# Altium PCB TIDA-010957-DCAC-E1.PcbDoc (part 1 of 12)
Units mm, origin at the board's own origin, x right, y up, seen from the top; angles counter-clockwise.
Board outline 300 x 300 mm, 4 copper layers (Top Layer, Layer 1, Layer 2, Bottom Layer), stack 1.787 mm thick; 1159 components, 619 nets, 3431 pads, 2942 vias.
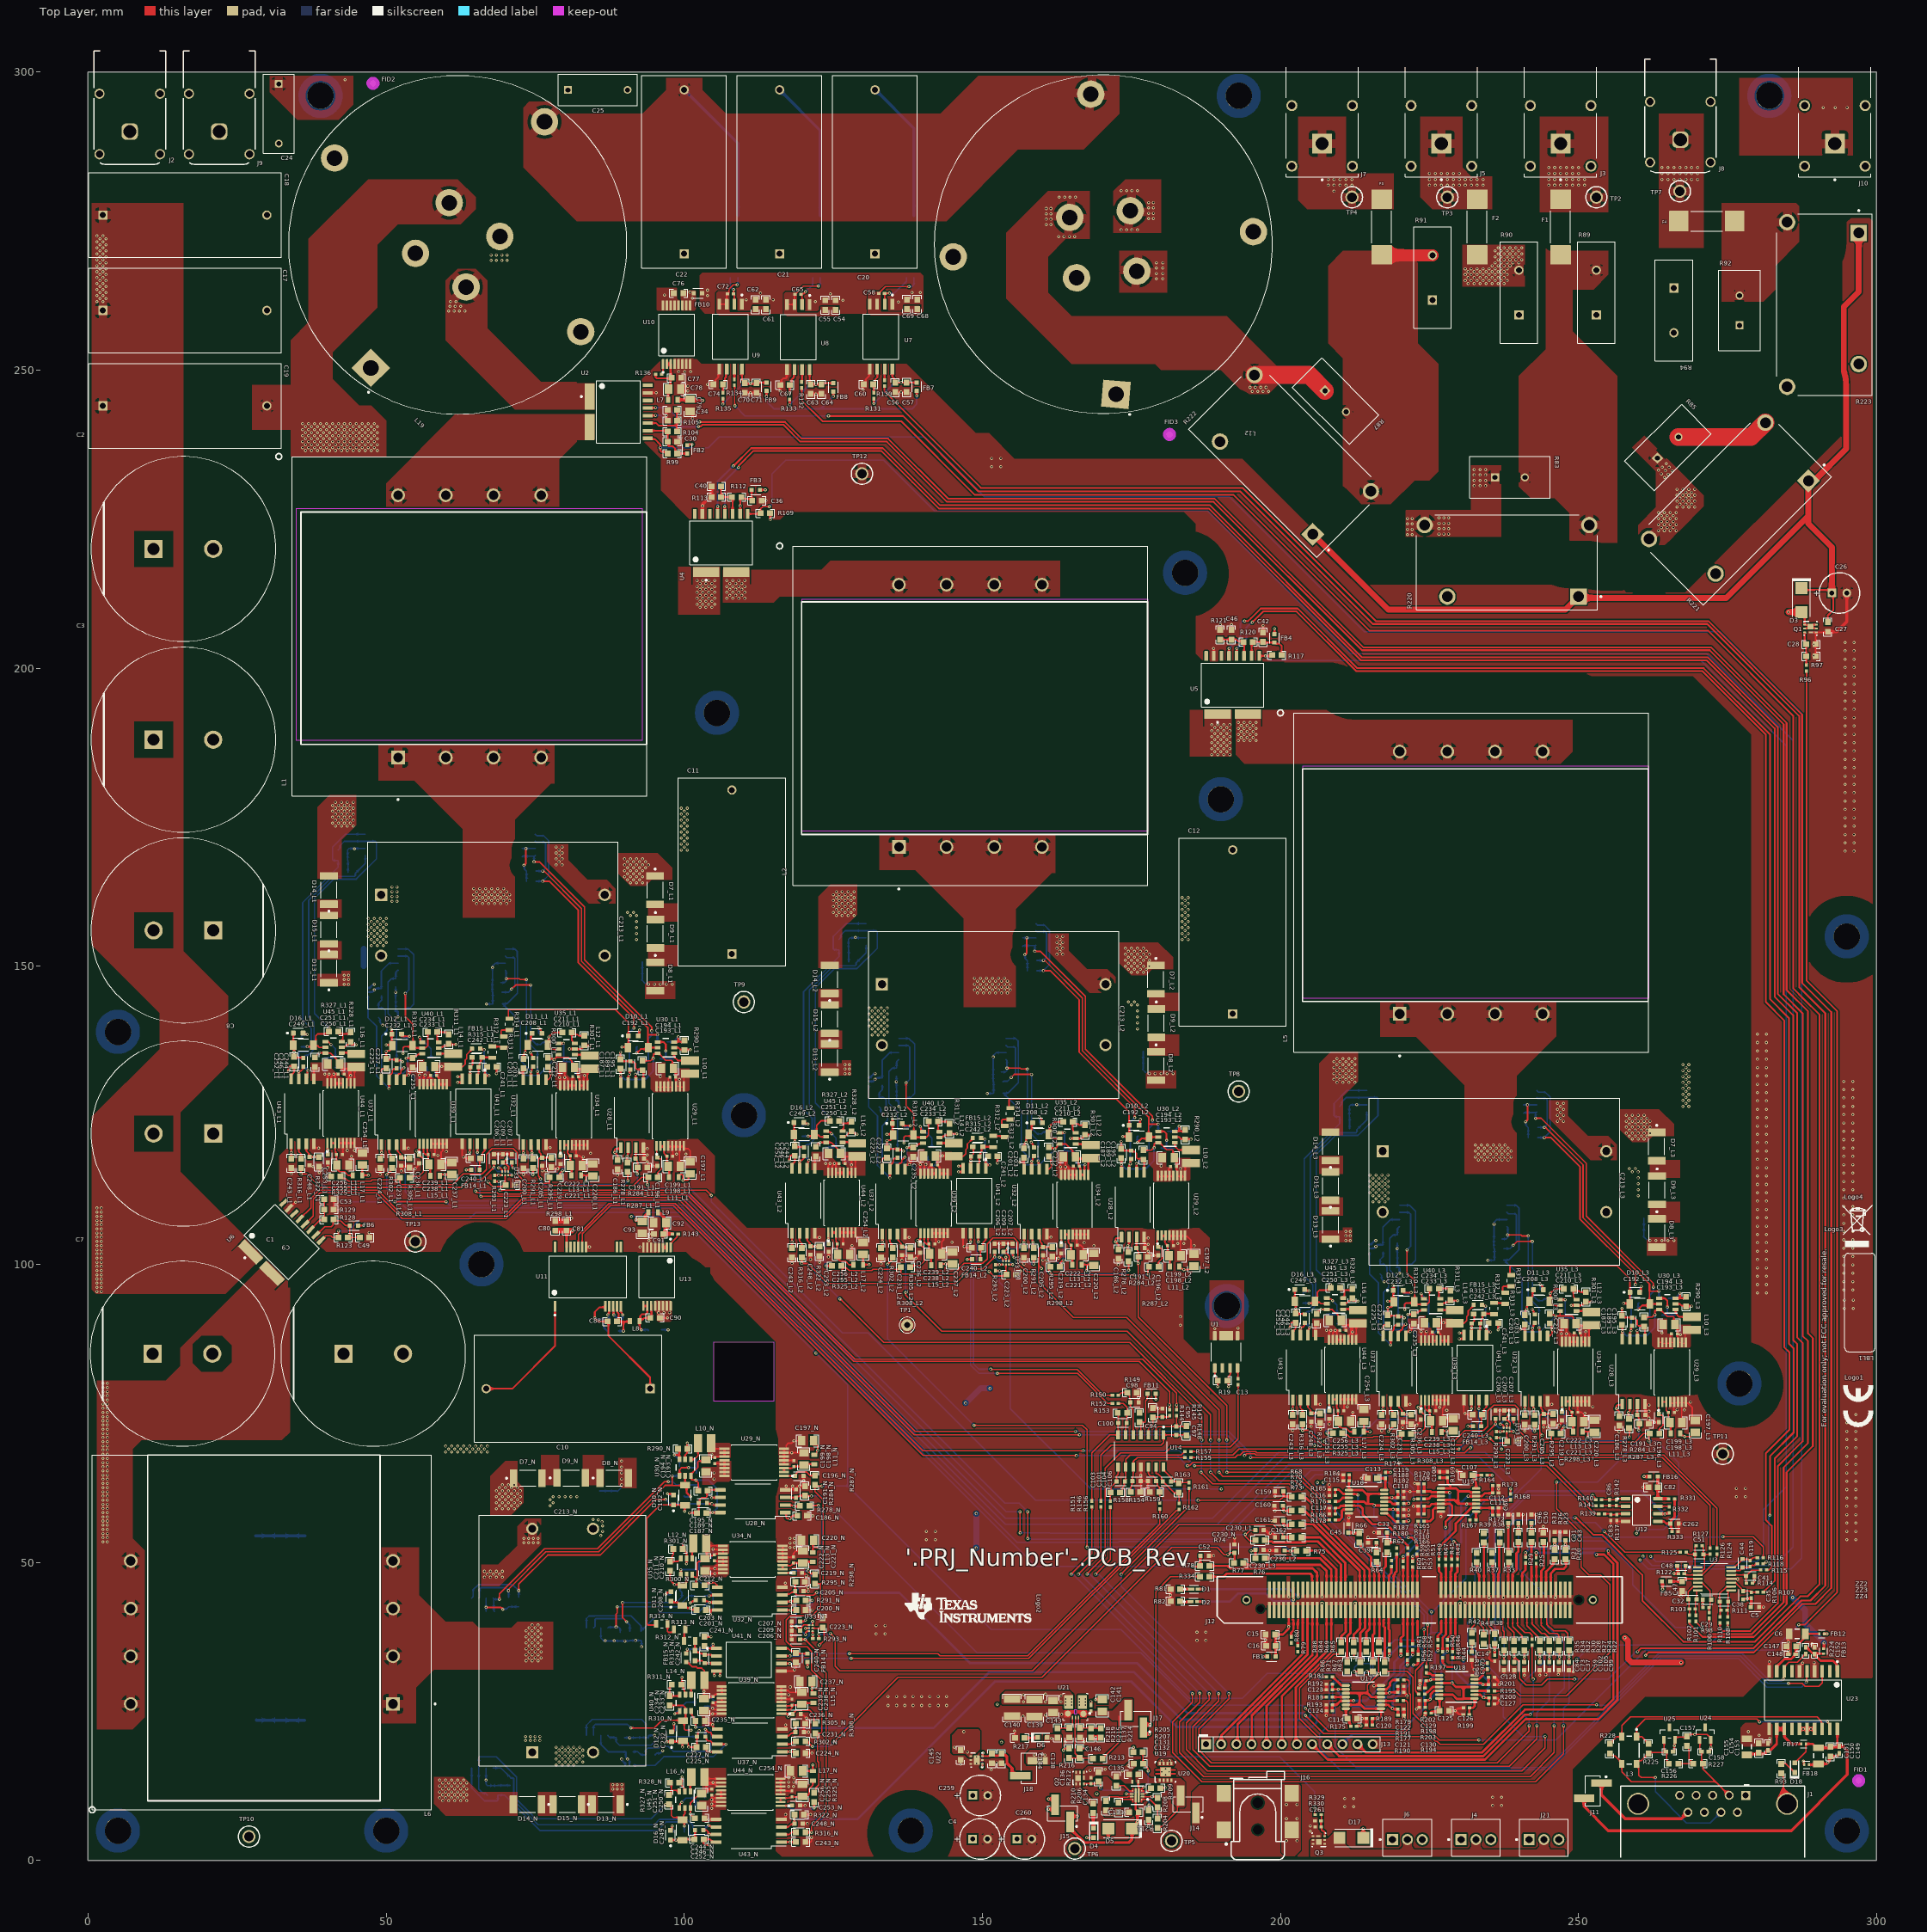
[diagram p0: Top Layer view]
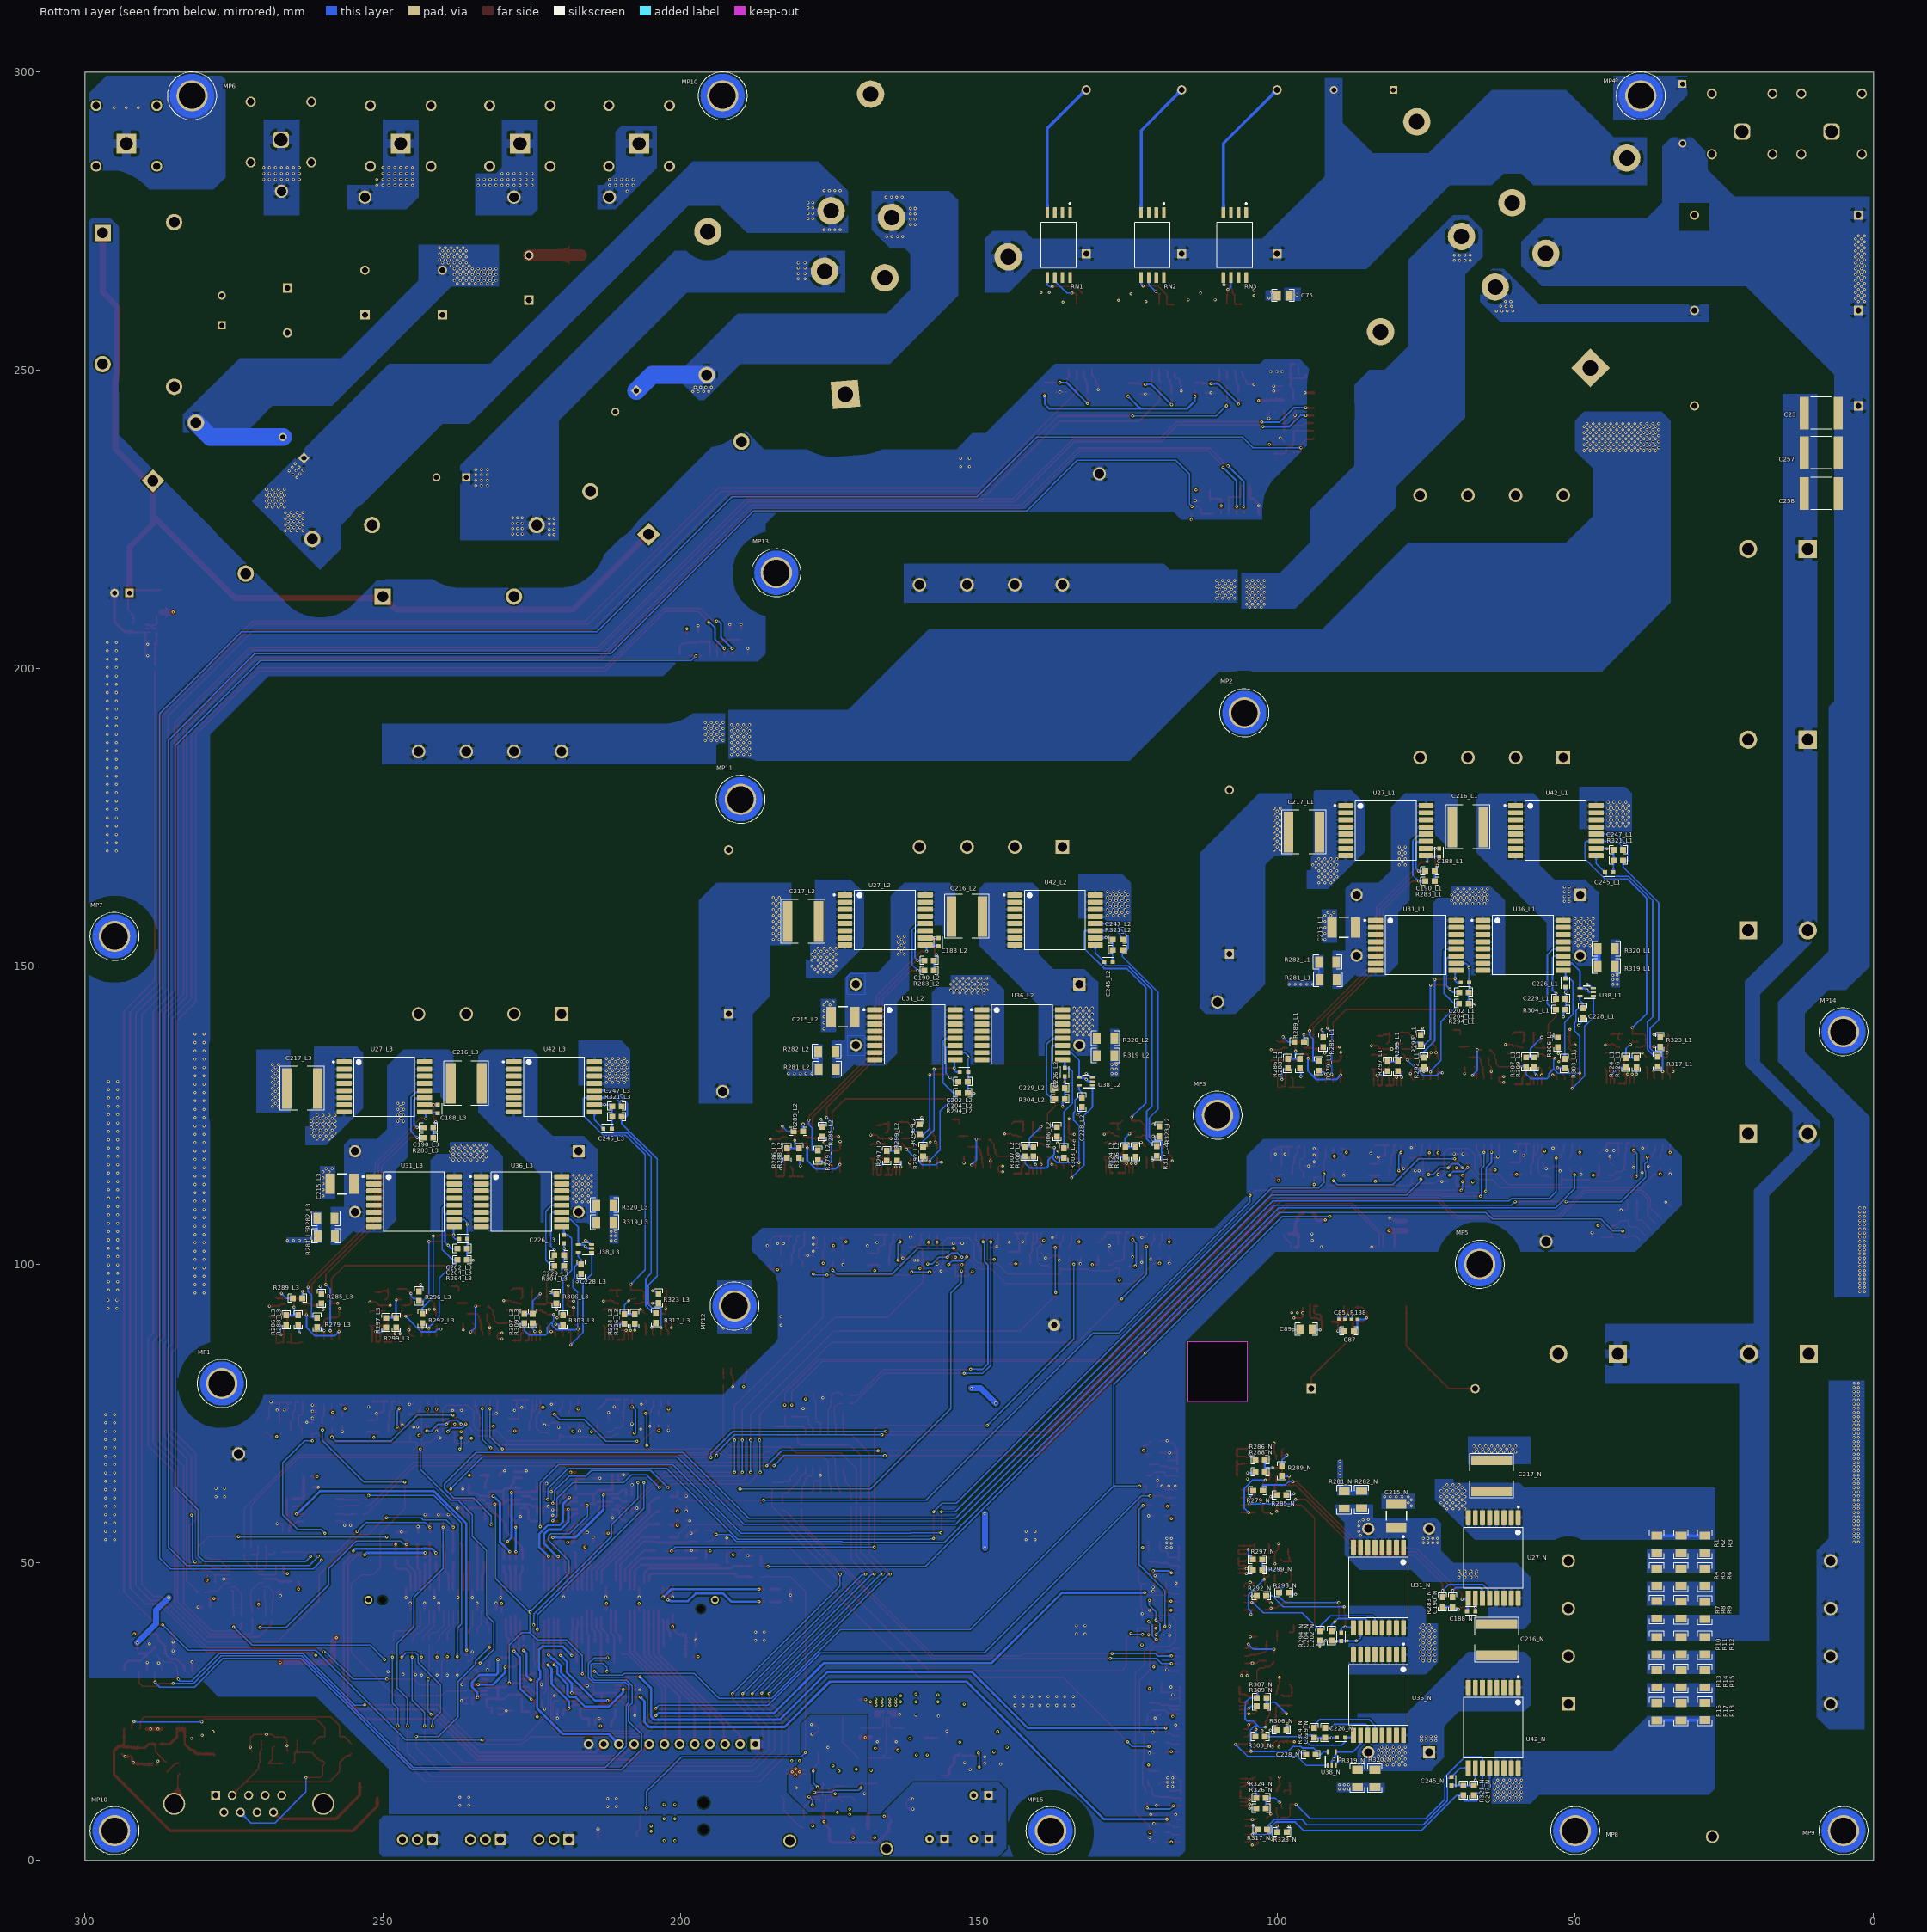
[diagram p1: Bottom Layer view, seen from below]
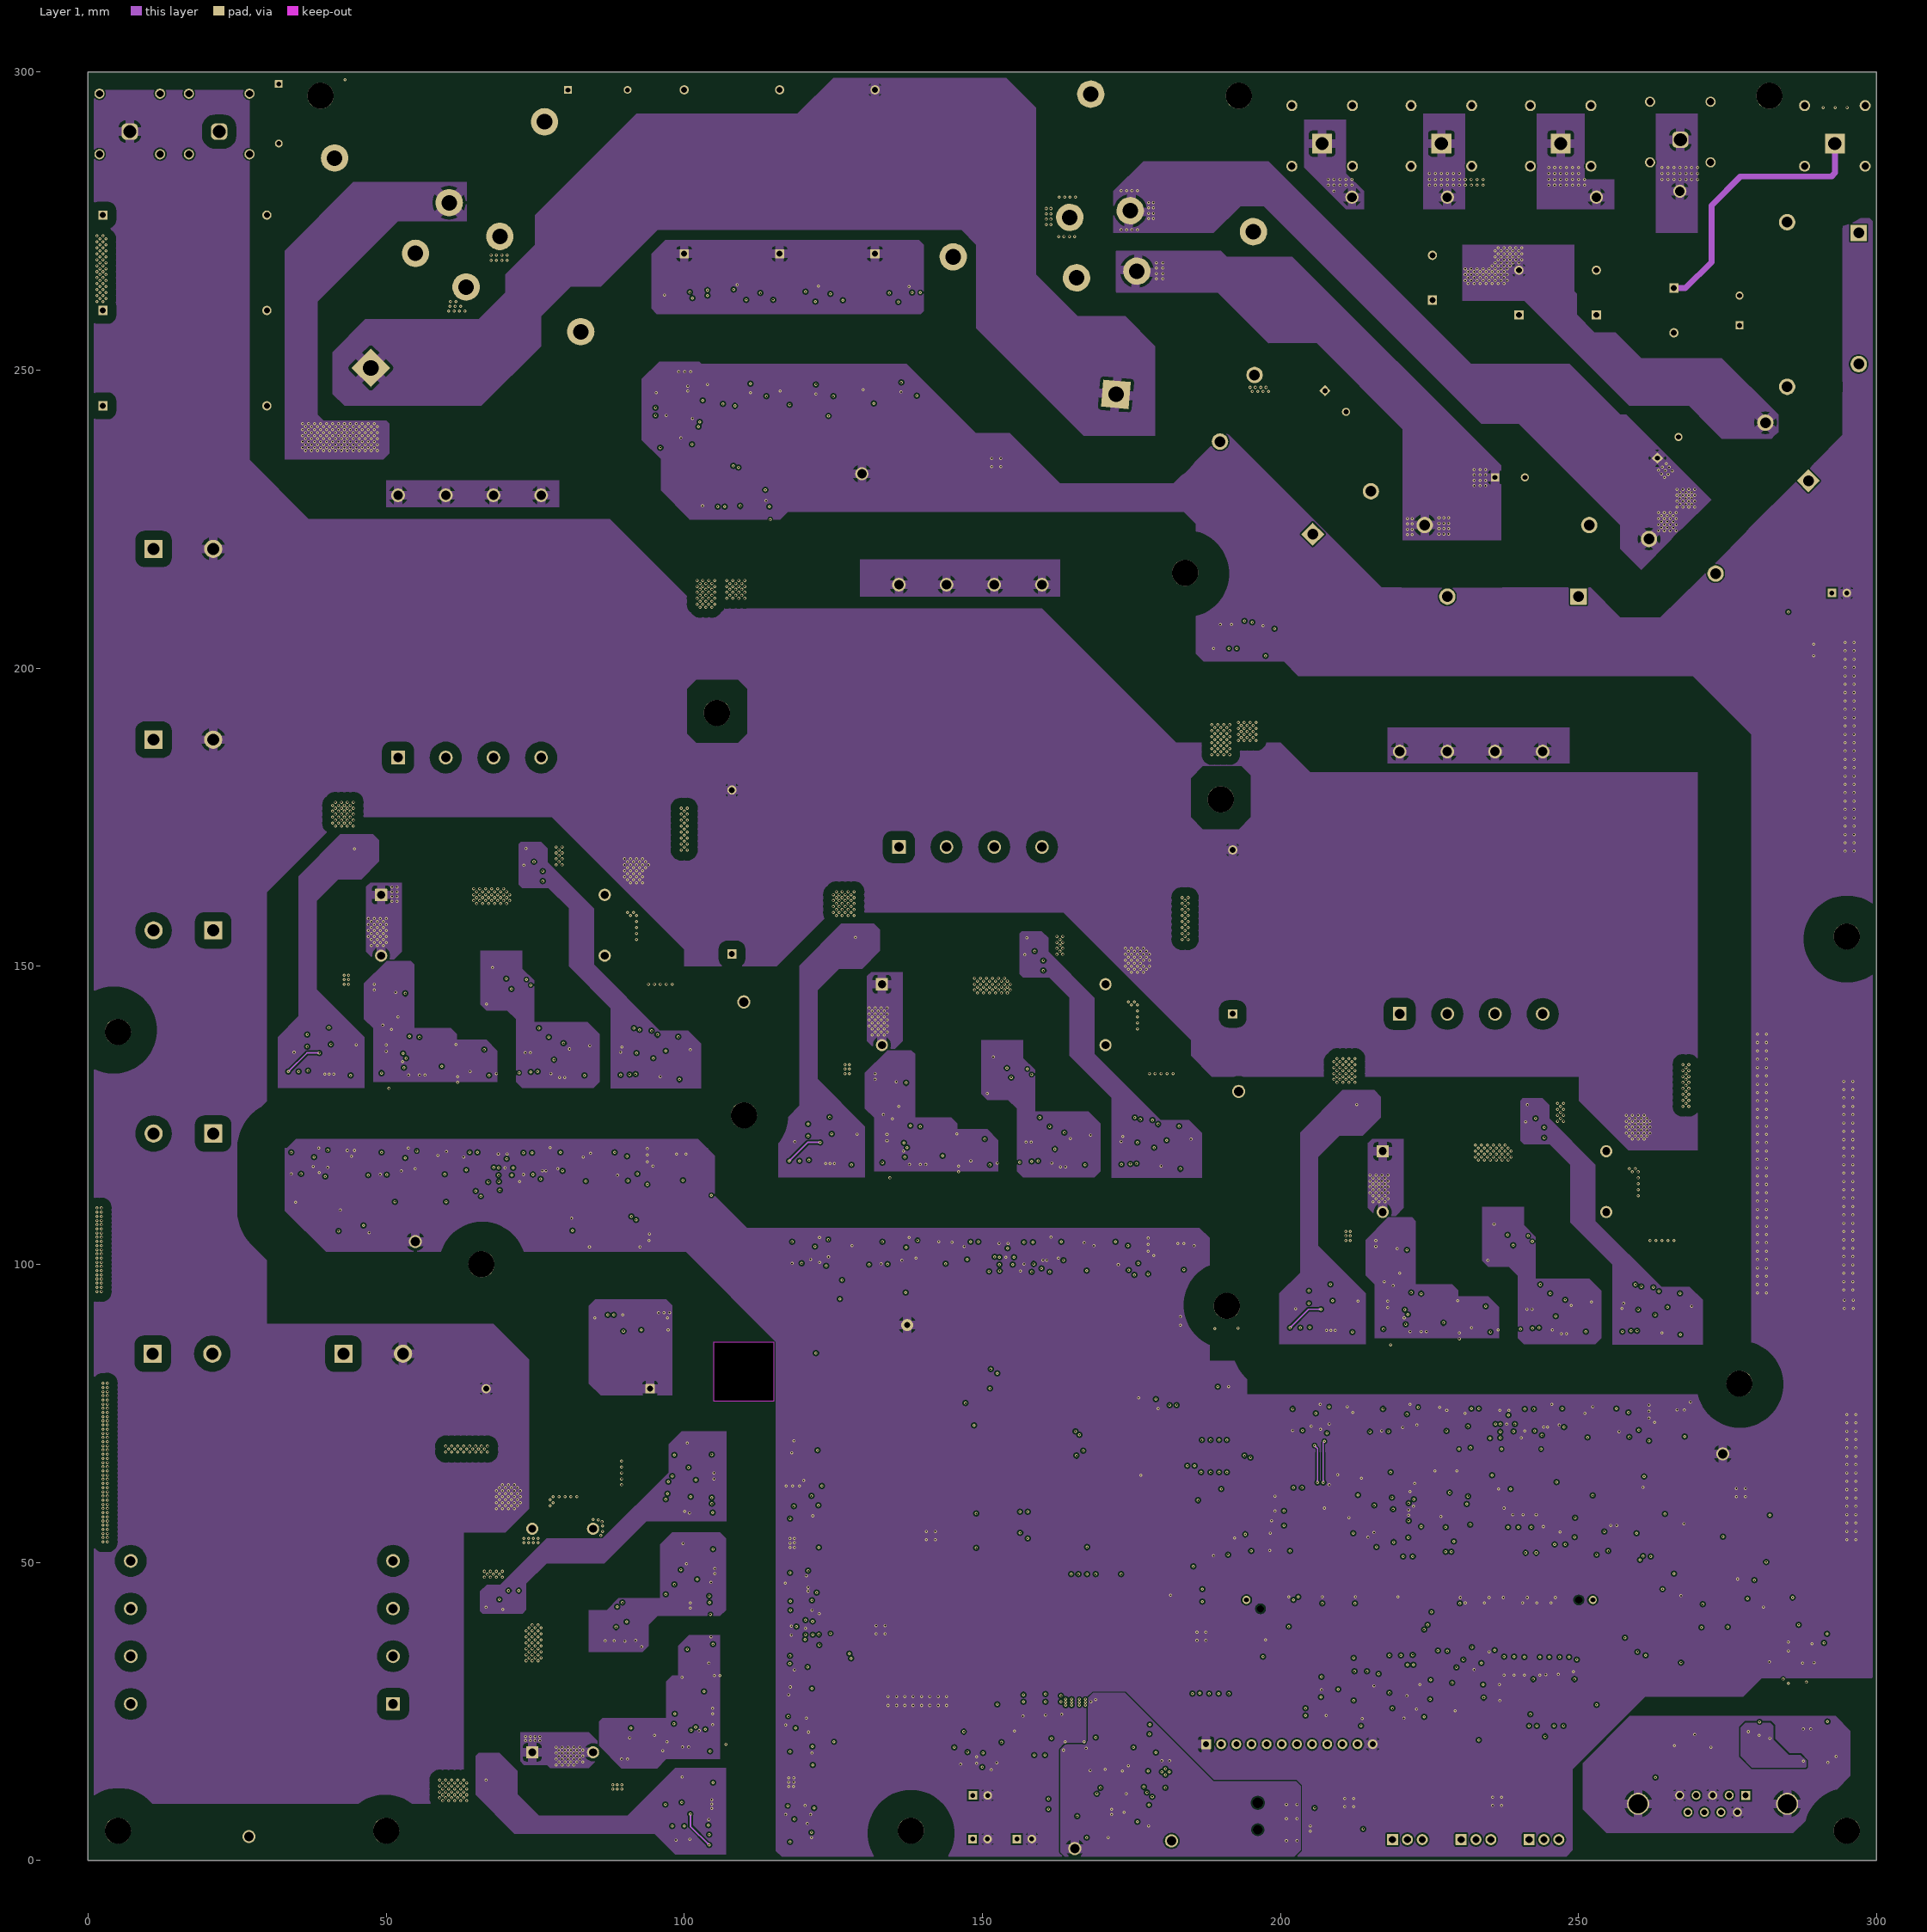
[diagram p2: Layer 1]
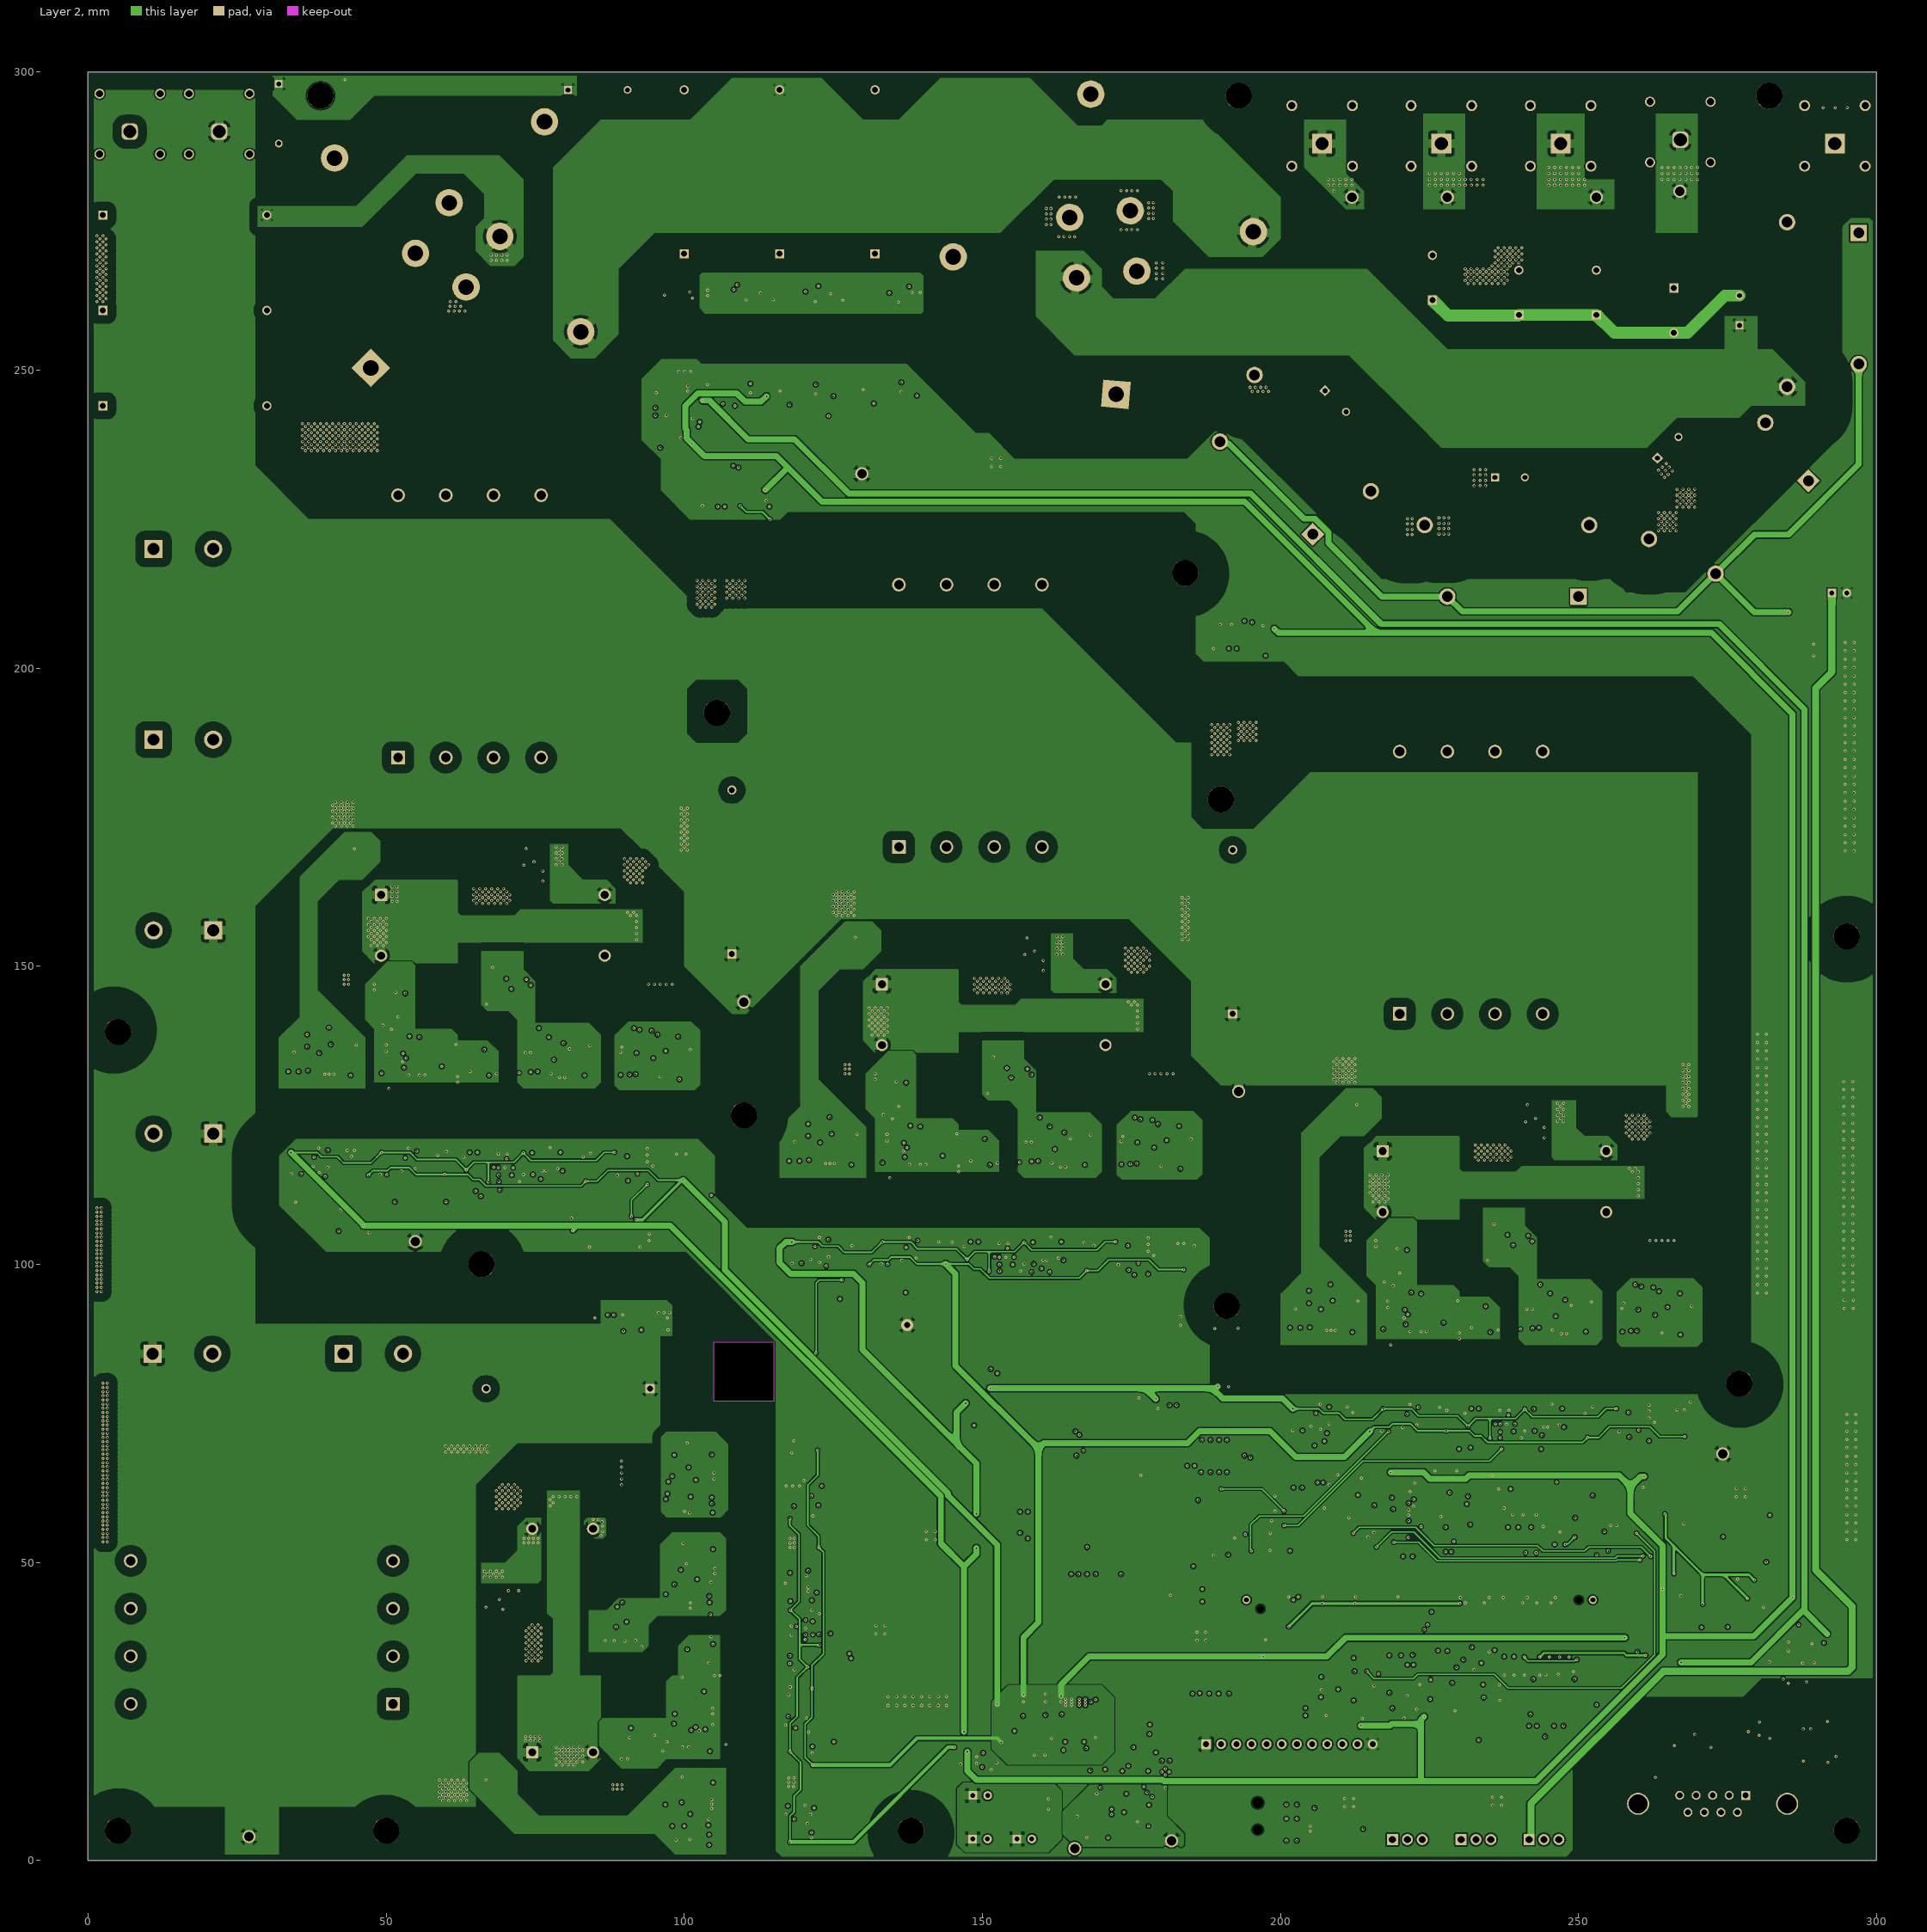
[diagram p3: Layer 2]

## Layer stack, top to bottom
Top Solder: solder mask 0.0102, Solder Resist, Dk 3.5
Top Layer: signal copper 0.0356
Dielectric 1: prepreg 0.0711, PP-006, Dk 4.1
Layer 1: signal copper 0.035
Dielectric1: core 1.5037, FR-4 High Tg, Dk 4.8
Layer 2: signal copper 0.035
Dielectric 2: prepreg 0.0711, PP-006, Dk 4.1
Bottom Layer: signal copper 0.0356
Bottom Solder: solder mask 0.0102, Solder Resist, Dk 3.5

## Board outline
0,0 300,0 300,300 0,300
cut-out: 105,77 105,87 115,87 115,77

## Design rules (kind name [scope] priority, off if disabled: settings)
AcuteAngle [All] p1: minimum=4.50000000000000E+0001 checktracksonly=FALSE
AssemblyTestPointUsage [All] p1: valid=2
BoardOutlineClearance BoardOutlineClearance_MountingHoles [OnCopper and InComponentClass('Mounting Holes')] p1: gap=1 ignorepadtopadclearanceinfootprint=FALSE
BoardOutlineClearance BoardOutlineClearance_Poly [OnCopper and IsPoly] p2: gap=0.635 ignorepadtopadclearanceinfootprint=FALSE
BoardOutlineClearance [OnCopper and Not InComponentClass('Logo') and not InComponentClass('FiducialMark') and not InRegion(1000,500,4000,800) and not InPoly] p3: gap=1.016 ignorepadtopadclearanceinfootprint=FALSE
Clearance "POS NEG DC Middle TOP" [(InNetClass('DC PLUS') or InNetClass('DC MINUS')) vs ((InNetClass('DC MIDDLE'))) And( OnLayer('Top Layer') Or OnLayer('Bottom Layer') )] p1: gap=3 ignorepadtopadclearanceinfootprint=TRUE
Clearance "Line to Line Top Bottom L1 to L2 L3" [(InNetClass('L1_HV')) And( OnLayer('Top Layer') Or OnLayer('Bottom Layer') ) vs ( InNetClass('L2_HV') Or InNetClass('L3_HV')) And( OnLayer('Top Layer') Or OnLayer('Bottom Layer') )] p2: gap=2.5 ignorepadtopadclearanceinfootprint=TRUE
Clearance "Line to Line inner L1 to L2 L3_1" [(InNetClass('L1_HV')) And( OnLayer('Top Layer') Or OnLayer('Bottom Layer') ) vs ( InNetClass('L2_HV') Or InNetClass('L3_HV')) And( not( OnLayer('Top Layer') Or OnLayer('Bottom Layer')) )] p3: gap=2.5 ignorepadtopadclearanceinfootprint=TRUE
Clearance "Line to Line Top Bottom L2 to L1 L3" [( InNetClass('L2_HV') ) And( OnLayer('Top Layer') Or OnLayer('Bottom Layer') ) vs (InNetClass('L1_HV')  Or InNetClass('L3_HV')) And( OnLayer('Top Layer') Or OnLayer('Bottom Layer') )] p4: gap=2.5 ignorepadtopadclearanceinfootprint=TRUE
Clearance "Line to Line Inner L2 to L1 L3_1" [( InNetClass('L2_HV') ) And( OnLayer('Top Layer') Or OnLayer('Bottom Layer') ) vs (InNetClass('L1_HV')  Or InNetClass('L3_HV')) And( not( OnLayer('Top Layer') Or OnLayer('Bottom Layer')) )] p5: gap=2.5 ignorepadtopadclearanceinfootprint=TRUE
Clearance "Line to Line Top Bottom L3 to L2 L1" [( InNetClass('L3_HV')) And( OnLayer('Top Layer') Or OnLayer('Bottom Layer') ) vs (InNetClass('L1_HV') Or InNetClass('L2_HV') ) And( OnLayer('Top Layer') Or OnLayer('Bottom Layer') )] p6: gap=2.5 ignorepadtopadclearanceinfootprint=TRUE
Clearance "Line to Line inner L3 to L2 L1_1" [( InNetClass('L3_HV')) And( OnLayer('Top Layer') Or OnLayer('Bottom Layer') ) vs (InNetClass('L1_HV') Or InNetClass('L2_HV') ) And(  not( OnLayer('Top Layer') Or OnLayer('Bottom Layer')) )] p7: gap=2.5 ignorepadtopadclearanceinfootprint=TRUE
Clearance "POS NEG TOP" [(InNetClass('DC PLUS')) vs ((InNetClass('DC MINUS'))) And( OnLayer('Top Layer') Or OnLayer('Bottom Layer') )] p8: gap=3 ignorepadtopadclearanceinfootprint=TRUE
Clearance "POS NEG Inner" [(InNetClass('DC PLUS')) vs ((InNetClass('DC MINUS'))) And( NOT ( OnLayer('Top Layer') Or OnLayer('Bottom Layer')))] p9: gap=1.5 ignorepadtopadclearanceinfootprint=TRUE
Clearance "POS NEG DC Middle Inner" [(InNetClass('DC PLUS') or InNetClass('DC MINUS')) vs ((InNetClass('DC MIDDLE'))) And( NOT ( OnLayer('Top Layer') Or OnLayer('Bottom Layer')))] p10: gap=1.5 ignorepadtopadclearanceinfootprint=TRUE
Clearance "Line and DC Rails EXT" [(InNetClass('L1_HV') Or InNetClass('L2_HV') Or InNetClass('L3_HV') Or InNetClass('LN_HV')) vs (InNetClass('DC PLUS') or InNetClass('DC MINUS')) And( ( OnLayer('Top Layer') Or OnLayer('Bottom Layer')) )] p11: gap=3 ignorepadtopadclearanceinfootprint=TRUE
Clearance "Line and DC Rails INT" [(InNetClass('L1_HV') Or InNetClass('L2_HV') Or InNetClass('L3_HV')Or InNetClass('LN_HV')) vs (InNetClass('DC PLUS') or InNetClass('DC MINUS')) And( not( OnLayer('Top Layer') Or OnLayer('Bottom Layer')) )] p12: gap=1.5 ignorepadtopadclearanceinfootprint=TRUE
Clearance "SW1 to SW4 top" [InNetClass('S3_SW') vs ((InNetClass('S4_SW'))) And( OnLayer('Top Layer') Or OnLayer('Bottom Layer') )] p13: gap=2.3 ignorepadtopadclearanceinfootprint=TRUE
Clearance "SW1 to SW4 inner" [InNetClass('S3_SW') vs ((InNetClass('S4_SW'))) And( not(OnLayer('Top Layer') Or OnLayer('Bottom Layer')) )] p14: gap=1.5 ignorepadtopadclearanceinfootprint=TRUE
Clearance "SW3 to SW4 top" [InNetClass('S3_SW') vs ((InNetClass('S4_SW'))) And( OnLayer('Top Layer') Or OnLayer('Bottom Layer') )] p15: gap=2.3 ignorepadtopadclearanceinfootprint=TRUE
Clearance "SW3 to SW4 inner" [InNetClass('S3_SW') vs ((InNetClass('S4_SW'))) And( not(OnLayer('Top Layer') Or OnLayer('Bottom Layer')) )] p16: gap=1.5 ignorepadtopadclearanceinfootprint=TRUE
Clearance "SW2 to SW3 top" [InNetClass('S2_SW') vs ((InNetClass('S3_SW'))) And( OnLayer('Top Layer') Or OnLayer('Bottom Layer') )] p17: gap=2.3 ignorepadtopadclearanceinfootprint=TRUE
Clearance "SW2 to SW3 inner" [InNetClass('S2_SW') vs ((InNetClass('S3_SW'))) And( not(OnLayer('Top Layer') Or OnLayer('Bottom Layer')) )] p18: gap=1.5 ignorepadtopadclearanceinfootprint=TRUE
Clearance "SW1 to SW2 top" [InNetClass('S1_SW') vs ((InNetClass('S2_SW'))) And( OnLayer('Top Layer') Or OnLayer('Bottom Layer') )] p19: gap=2.3 ignorepadtopadclearanceinfootprint=TRUE
Clearance "SW1 to SW2 inner" [InNetClass('S1_SW') vs ((InNetClass('S2_SW'))) And( not(OnLayer('Top Layer') Or OnLayer('Bottom Layer')) )] p20: gap=1.5 ignorepadtopadclearanceinfootprint=TRUE
Clearance "High Voltage to Low Voltage" [InNetClass('HV_NET') vs InNetClass('LV_NET')] p21: gap=8 ignorepadtopadclearanceinfootprint=FALSE
Clearance Clearance_Keepouts [((IsTrack Or IsArc) And Not InPoly) And IsFree and IsKeepOut vs ((IsTrack Or IsArc) And Not InPoly) And IsFree and IsKeepOut] p22: gap=0 ignorepadtopadclearanceinfootprint=FALSE
Clearance Clearance_Poly [InPolygon] p23: gap=0.254 ignorepadtopadclearanceinfootprint=TRUE
Clearance Clearance_FiducialMark [IsKeepOut and InComponentClass('FiducialMark') vs IsPad and InComponentClass('FiducialMark')] p24: gap=0 ignorepadtopadclearanceinfootprint=FALSE
Clearance [All] p25: gap=0.2 ignorepadtopadclearanceinfootprint=TRUE
Clearance Clearance_1 [All] p26: gap=0.2 ignorepadtopadclearanceinfootprint=TRUE
ComponentClearance ComponentClearance_MountingHoles_FiducialMarks [InComponentClass('Mounting Holes') vs InComponentClass('FiducialMark')] p1: gap=1.27 collisioncheckmode=3 verticalgap=0.254 showdistances=FALSE
ComponentClearance ComponentClearance_Shunt [InComponentClass('Header') vs InComponentClass('Shunt')] p2: gap=0 collisioncheckmode=3 verticalgap=0 showdistances=FALSE
ComponentClearance ComponentClearance_Logo [InComponentClass('Logo')] p3: gap=0.762 collisioncheckmode=3 verticalgap=0.254 showdistances=FALSE
ComponentClearance ComponentClearance_ScrewToNut [(HasFootprint('NY PMS 440 0025 PH')) vs (HasFootprint('Keystone_1902C'))] p4: gap=0.127 collisioncheckmode=3 verticalgap=0.254 showdistances=FALSE
ComponentClearance ComponentClearance_MountingHoles [InComponentClass('Mounting Holes')] p5: gap=2.54 collisioncheckmode=3 verticalgap=2540 showdistances=FALSE
ComponentClearance ComponentClearance_SmallPassives [HasFootprint('0201*') or HasFootprint('0402*') or HasFootprint('0508') or HasFootprint('0603*') or HasFootprint('0612') or HasFootprint('0805*') or HasFootprint('0815*') or HasFootprint('0830*') or HasFootprint('1206*') or HasFootprint('1210*') or HasFootprint('1808*') or HasFootprint('1812*') or HasFootprint('1825*') or HasFootprint('2010*') or HasFootprint('2220*') or HasFootprint('2225*') or HasFootprint('2512*') or HasFootprint('2728*') or HasFootprint('3518*') vs HasFootprint('0201*') or HasFootprint('0402*') or HasFootprint('0508') or HasFootprint('0603*') or HasFootprint('0612') or HasFootprint('0805*') or HasFootprint('0815*') or HasFootprint('0830*') or HasFootprint('1206*') or HasFootprint('1210*') or HasFootprint('1808*') or HasFootprint('1812*') or HasFootprint('1825*') or HasFootprint('2010*') or HasFootprint('2220*') or HasFootprint('2225*') or HasFootprint('2512*') or HasFootprint('2728*') or HasFootprint('3518*')] p6: gap=0.38 collisioncheckmode=3 verticalgap=0.254 showdistances=FALSE
ComponentClearance ComponentClearance_THtoSMT [IsThruComponent vs IsSMTComponent] p7: gap=0.762 collisioncheckmode=3 verticalgap=0.762 showdistances=FALSE
ComponentClearance ComponentClearance_THtoTH [IsThruComponent vs IsThruComponent] p8: gap=0.508 collisioncheckmode=3 verticalgap=0.762 showdistances=FALSE
ComponentClearance [All] p9: gap=0.508 collisioncheckmode=3 verticalgap=0.254 showdistances=FALSE
FabricationTestPointUsage TestPointUsage [All] p1: valid=2 allowmultiple=FALSE
FabricationTestpoint Testpoint [All] p1: side=3 testpointundercomponent=TRUE minsize=1.016 maxsize=2.54 preferedsize=1.524 minholesize=0 maxholesize=1.016 preferedholesize=0.813 testpointgrid=0.025 allowsidetop=TRUE allowsidebottom=TRUE usegrid=TRUE gridtolerance=0
FanoutControl Fanout_LCC [IsLCC] p1: bgadir=Out bgaviamode=Centered fanoutstyle=Auto fanoutdirection=Alternating viagrid=0.025 // Fanout_LCC (Default Rule)
FanoutControl Fanout_BGA [IsBGA] p2: bgadir=Out bgaviamode=Centered fanoutstyle=Auto fanoutdirection=Alternating viagrid=0.025 // Fanout_BGA (Default Rule)
FanoutControl Fanout_Default [All] p4: bgadir=Out bgaviamode=Centered fanoutstyle=Auto fanoutdirection=Alternating viagrid=0.025 // Fanout_Default (Default Rule)
FanoutControl Fanout_Small [(CompPinCount < 5)] p5: bgadir=Out bgaviamode=Centered fanoutstyle=Auto fanoutdirection=OutThenIn viagrid=0.025 // Fanout_Small (Default Rule)
Height [All] p1: minheight=0 maxheight=50 prefheight=12.7
HoleSize [All] p1: absolutevalues=TRUE maxlimit=6.375 minlimit=0.2 maxpercent=80.000 minpercent=20.000
MinimumAnnularRing MinimumAnnularRing_ThermalPadVias [IsVia and InAnyComponent] p1: minimumring=0.15
MinimumAnnularRing [All] p2: minimumring=0.1
MinimumSolderMaskSliver MinimumSolderMaskSliver_Logo [InComponentClass('Logo') vs InComponentClass('Logo')] p1: minsoldermaskwidth=0.018
MinimumSolderMaskSliver [All] p2: minsoldermaskwidth=0.01
PlaneConnect [All] p1: planeconnectstyle=Direct reliefexpansion=0.254 reliefentries=4 reliefconductorwidth=0.254 reliefairgap=0.254
PolygonConnect GaNL1_4 [IsNamedPolygon('BOTTOM_LAYER_VDC-_REF_P188')] p1: thpad.connectstyle=Relief thpad.reliefconductorwidth=0.5 thpad.reliefentries=4 thpad.polygonreliefangle="90 Angle" thpad.airgapwidth=0.254 smdpad.connectstyle=Relief smdpad.reliefconductorwidth=0.5 smdpad.reliefentries=4 smdpad.polygonreliefangle="90 Angle" smdpad.airgapwidth=0.254 via.connectstyle=Direct via.reliefconductorwidth=0.254 via.reliefentries=4 via.polygonreliefangle="90 Angle" via.airgapwidth=0.254
PolygonConnect GaNL1_2 [IsNamedPolygon('BOTTOM_LAYER_SN_L1_P180')] p2: thpad.connectstyle=Relief thpad.reliefconductorwidth=0.5 thpad.reliefentries=4 thpad.polygonreliefangle="90 Angle" thpad.airgapwidth=0.254 smdpad.connectstyle=Relief smdpad.reliefconductorwidth=0.5 smdpad.reliefentries=4 smdpad.polygonreliefangle="90 Angle" smdpad.airgapwidth=0.254 via.connectstyle=Direct via.reliefconductorwidth=0.254 via.reliefentries=4 via.polygonreliefangle="90 Angle" via.airgapwidth=0.254
PolygonConnect GaNL1_3 [IsNamedPolygon('BOTTOM_LAYER_NETC213_L1_2_P181')] p3: thpad.connectstyle=Relief thpad.reliefconductorwidth=0.5 thpad.reliefentries=4 thpad.polygonreliefangle="90 Angle" thpad.airgapwidth=0.254 smdpad.connectstyle=Relief smdpad.reliefconductorwidth=0.5 smdpad.reliefentries=4 smdpad.polygonreliefangle="90 Angle" smdpad.airgapwidth=0.254 via.connectstyle=Direct via.reliefconductorwidth=0.254 via.reliefentries=4 via.polygonreliefangle="90 Angle" via.airgapwidth=0.254
PolygonConnect GaNL1_1 [IsNamedpolygon('BOTTOM_LAYER_NETC213_L1_1_P179')] p4: thpad.connectstyle=Relief thpad.reliefconductorwidth=0.5 thpad.reliefentries=4 thpad.polygonreliefangle="90 Angle" thpad.airgapwidth=0.254 smdpad.connectstyle=Relief smdpad.reliefconductorwidth=0.5 smdpad.reliefentries=4 smdpad.polygonreliefangle="90 Angle" smdpad.airgapwidth=0.254 via.connectstyle=Direct via.reliefconductorwidth=0.254 via.reliefentries=4 via.polygonreliefangle="90 Angle" via.airgapwidth=0.254
PolygonConnect GaNL3_1 [IsNamedpolygon('BOTTOM_LAYER_VDC-_REF_P273')] p5: thpad.connectstyle=Relief thpad.reliefconductorwidth=0.5 thpad.reliefentries=4 thpad.polygonreliefangle="90 Angle" thpad.airgapwidth=0.254 smdpad.connectstyle=Relief smdpad.reliefconductorwidth=0.5 smdpad.reliefentries=4 smdpad.polygonreliefangle="90 Angle" smdpad.airgapwidth=0.254 via.connectstyle=Direct via.reliefconductorwidth=0.254 via.reliefentries=4 via.polygonreliefangle="90 Angle" via.airgapwidth=0.254
PolygonConnect GaNL4_1 [IsNamedpolygon('BOTTOM_LAYER_VDC+_P015')] p6: thpad.connectstyle=Relief thpad.reliefconductorwidth=0.5 thpad.reliefentries=4 thpad.polygonreliefangle="90 Angle" thpad.airgapwidth=0.254 smdpad.connectstyle=Relief smdpad.reliefconductorwidth=0.5 smdpad.reliefentries=4 smdpad.polygonreliefangle="90 Angle" smdpad.airgapwidth=0.254 via.connectstyle=Direct via.reliefconductorwidth=0.254 via.reliefentries=4 via.polygonreliefangle="90 Angle" via.airgapwidth=0.254
PolygonConnect GaNL4_2 [IsNamedpolygon('BOTTOM_LAYER_NETC213_N_2_P007')] p7: thpad.connectstyle=Relief thpad.reliefconductorwidth=0.5 thpad.reliefentries=4 thpad.polygonreliefangle="90 Angle" thpad.airgapwidth=0.254 smdpad.connectstyle=Relief smdpad.reliefconductorwidth=0.5 smdpad.reliefentries=4 smdpad.polygonreliefangle="90 Angle" smdpad.airgapwidth=0.254 via.connectstyle=Direct via.reliefconductorwidth=0.254 via.reliefentries=4 via.polygonreliefangle="90 Angle" via.airgapwidth=0.254
PolygonConnect GaNL4_3 [IsNamedpolygon('BOTTOM_LAYER_NETC213_N_1_P001')] p8: thpad.connectstyle=Relief thpad.reliefconductorwidth=0.5 thpad.reliefentries=4 thpad.polygonreliefangle="90 Angle" thpad.airgapwidth=0.254 smdpad.connectstyle=Relief smdpad.reliefconductorwidth=0.5 smdpad.reliefentries=4 smdpad.polygonreliefangle="90 Angle" smdpad.airgapwidth=0.254 via.connectstyle=Direct via.reliefconductorwidth=0.254 via.reliefentries=4 via.polygonreliefangle="90 Angle" via.airgapwidth=0.254
PolygonConnect GaNL4_4 [IsNamedpolygon('BOTTOM_LAYER_SN_LN_P002')] p9: thpad.connectstyle=Relief thpad.reliefconductorwidth=0.5 thpad.reliefentries=4 thpad.polygonreliefangle="90 Angle" thpad.airgapwidth=0.254 smdpad.connectstyle=Relief smdpad.reliefconductorwidth=0.5 smdpad.reliefentries=4 smdpad.polygonreliefangle="90 Angle" smdpad.airgapwidth=0.254 via.connectstyle=Direct via.reliefconductorwidth=0.254 via.reliefentries=4 via.polygonreliefangle="90 Angle" via.airgapwidth=0.254
PolygonConnect GaNL4_5 [IsNamedpolygon('BOTTOM_LAYER_VDC-_REF_P047')] p10: thpad.connectstyle=Relief thpad.reliefconductorwidth=0.5 thpad.reliefentries=4 thpad.polygonreliefangle="90 Angle" thpad.airgapwidth=0.254 smdpad.connectstyle=Relief smdpad.reliefconductorwidth=0.5 smdpad.reliefentries=4 smdpad.polygonreliefangle="90 Angle" smdpad.airgapwidth=0.254 via.connectstyle=Direct via.reliefconductorwidth=0.254 via.reliefentries=4 via.polygonreliefangle="90 Angle" via.airgapwidth=0.254
PolygonConnect GaNL3_2 [IsNamedpolygon('BOTTOM_LAYER_NETC213_L3_1_P264')] p11: thpad.connectstyle=Relief thpad.reliefconductorwidth=0.5 thpad.reliefentries=4 thpad.polygonreliefangle="90 Angle" thpad.airgapwidth=0.254 smdpad.connectstyle=Relief smdpad.reliefconductorwidth=0.5 smdpad.reliefentries=4 smdpad.polygonreliefangle="90 Angle" smdpad.airgapwidth=0.254 via.connectstyle=Direct via.reliefconductorwidth=0.254 via.reliefentries=4 via.polygonreliefangle="90 Angle" via.airgapwidth=0.254
PolygonConnect GaNL3_3 [IsNamedpolygon('BOTTOM_LAYER_SN_L3_P265')] p12: thpad.connectstyle=Relief thpad.reliefconductorwidth=0.5 thpad.reliefentries=4 thpad.polygonreliefangle="90 Angle" thpad.airgapwidth=0.254 smdpad.connectstyle=Relief smdpad.reliefconductorwidth=0.5 smdpad.reliefentries=4 smdpad.polygonreliefangle="90 Angle" smdpad.airgapwidth=0.254 via.connectstyle=Direct via.reliefconductorwidth=0.254 via.reliefentries=4 via.polygonreliefangle="90 Angle" via.airgapwidth=0.254
PolygonConnect GaNL3_4 [IsNamedpolygon('BOTTOM_LAYER_NETC213_L3_2_P266')] p13: thpad.connectstyle=Relief thpad.reliefconductorwidth=0.5 thpad.reliefentries=4 thpad.polygonreliefangle="90 Angle" thpad.airgapwidth=0.254 smdpad.connectstyle=Relief smdpad.reliefconductorwidth=0.5 smdpad.reliefentries=4 smdpad.polygonreliefangle="90 Angle" smdpad.airgapwidth=0.254 via.connectstyle=Direct via.reliefconductorwidth=0.254 via.reliefentries=4 via.polygonreliefangle="90 Angle" via.airgapwidth=0.254
PolygonConnect GaNL3_5 [IsNamedpolygon('BOTTOM_LAYER_VDC+_P267')] p14: thpad.connectstyle=Relief thpad.reliefconductorwidth=0.5 thpad.reliefentries=4 thpad.polygonreliefangle="90 Angle" thpad.airgapwidth=0.254 smdpad.connectstyle=Relief smdpad.reliefconductorwidth=0.5 smdpad.reliefentries=4 smdpad.polygonreliefangle="90 Angle" smdpad.airgapwidth=0.254 via.connectstyle=Direct via.reliefconductorwidth=0.254 via.reliefentries=4 via.polygonreliefangle="90 Angle" via.airgapwidth=0.254
PolygonConnect GaNL2_1 [IsNamedpolygon('BOTTOM_LAYER_VDC-_REF_P228')] p15: thpad.connectstyle=Relief thpad.reliefconductorwidth=0.5 thpad.reliefentries=4 thpad.polygonreliefangle="90 Angle" thpad.airgapwidth=0.254 smdpad.connectstyle=Relief smdpad.reliefconductorwidth=0.5 smdpad.reliefentries=4 smdpad.polygonreliefangle="90 Angle" smdpad.airgapwidth=0.254 via.connectstyle=Direct via.reliefconductorwidth=0.254 via.reliefentries=4 via.polygonreliefangle="90 Angle" via.airgapwidth=0.254
PolygonConnect GaNL2_2 [IsNamedpolygon('BOTTOM_LAYER_NETC213_L2_1_P219')] p16: thpad.connectstyle=Relief thpad.reliefconductorwidth=0.5 thpad.reliefentries=4 thpad.polygonreliefangle="90 Angle" thpad.airgapwidth=0.254 smdpad.connectstyle=Relief smdpad.reliefconductorwidth=0.5 smdpad.reliefentries=4 smdpad.polygonreliefangle="90 Angle" smdpad.airgapwidth=0.254 via.connectstyle=Direct via.reliefconductorwidth=0.254 via.reliefentries=4 via.polygonreliefangle="90 Angle" via.airgapwidth=0.254
PolygonConnect GaNL2_3 [IsNamedpolygon('BOTTOM_LAYER_SN_L2_P220')] p17: thpad.connectstyle=Relief thpad.reliefconductorwidth=0.5 thpad.reliefentries=4 thpad.polygonreliefangle="90 Angle" thpad.airgapwidth=0.254 smdpad.connectstyle=Relief smdpad.reliefconductorwidth=0.5 smdpad.reliefentries=4 smdpad.polygonreliefangle="90 Angle" smdpad.airgapwidth=0.254 via.connectstyle=Direct via.reliefconductorwidth=0.254 via.reliefentries=4 via.polygonreliefangle="90 Angle" via.airgapwidth=0.254
PolygonConnect GaNL2_4 [IsNamedpolygon('BOTTOM_LAYER_NETC213_L2_2_P221')] p18: thpad.connectstyle=Relief thpad.reliefconductorwidth=0.5 thpad.reliefentries=4 thpad.polygonreliefangle="90 Angle" thpad.airgapwidth=0.254 smdpad.connectstyle=Relief smdpad.reliefconductorwidth=0.5 smdpad.reliefentries=4 smdpad.polygonreliefangle="90 Angle" smdpad.airgapwidth=0.254 via.connectstyle=Direct via.reliefconductorwidth=0.254 via.reliefentries=4 via.polygonreliefangle="90 Angle" via.airgapwidth=0.254
PolygonConnect GaNL2_5 [IsNamedpolygon('BOTTOM_LAYER_VDC+_P222')] p19: thpad.connectstyle=Relief thpad.reliefconductorwidth=0.5 thpad.reliefentries=4 thpad.polygonreliefangle="90 Angle" thpad.airgapwidth=0.254 smdpad.connectstyle=Relief smdpad.reliefconductorwidth=0.5 smdpad.reliefentries=4 smdpad.polygonreliefangle="90 Angle" smdpad.airgapwidth=0.254 via.connectstyle=Direct via.reliefconductorwidth=0.254 via.reliefentries=4 via.polygonreliefangle="90 Angle" via.airgapwidth=0.254
PolygonConnect GaNL1_5 [IsNamedpolygon('BOTTOM_LAYER_VDC+_P182')] p20: thpad.connectstyle=Relief thpad.reliefconductorwidth=0.5 thpad.reliefentries=4 thpad.polygonreliefangle="90 Angle" thpad.airgapwidth=0.254 smdpad.connectstyle=Relief smdpad.reliefconductorwidth=0.5 smdpad.reliefentries=4 smdpad.polygonreliefangle="90 Angle" smdpad.airgapwidth=0.254 via.connectstyle=Direct via.reliefconductorwidth=0.254 via.reliefentries=4 via.polygonreliefangle="90 Angle" via.airgapwidth=0.254
PolygonConnect [All] p21: thpad.connectstyle=Relief thpad.reliefconductorwidth=1.5 thpad.reliefentries=4 thpad.polygonreliefangle="90 Angle" thpad.airgapwidth=0.5 smdpad.connectstyle=Direct smdpad.reliefconductorwidth=0.254 smdpad.reliefentries=4 smdpad.polygonreliefangle="90 Angle" smdpad.airgapwidth=0.254 via.connectstyle=Direct via.reliefconductorwidth=0.254 via.reliefentries=4 via.polygonreliefangle="90 Angle" via.airgapwidth=0.254
RoomDefinition L2 [InComponentClass('L2')] p1: confinementstyle=ConfineIn formatcopy=TRUE lockcomponents=FALSE outline 116,220.5 116,96.5 188,96.5 188,220.5
RoomDefinition L1 [InComponentClass('L1')] p2: confinementstyle=ConfineIn formatcopy=TRUE lockcomponents=FALSE outline 32,235.5 32,111.5 104,111.5 104,235.5
RoomDefinition N [InComponentClass('N')] p3: confinementstyle=ConfineIn formatcopy=TRUE lockcomponents=FALSE outline 1,1 125,1 125,73 1,73
RoomDefinition L3 [InComponentClass('L3')] p4: confinementstyle=ConfineIn formatcopy=TRUE lockcomponents=FALSE outline 200,192.5 200,68.5 272,68.5 272,192.5
RoutingVias [All] p1: holewidth=0.2 width=0.61 viastyle="Through Hole" minholewidth=0.2 minwidth=0.61 maxholewidth=0.711 maxwidth=1.27
SilkToBoardRegionClearance [Not ((IsComment or IsDesignator) And (Hide <> 'False')) and not InRegion(1000,500,4000,800)] p1:
SilkToSilkClearance SilkToSilkClearance_Pb-FreeLogo [(HasFootprint('Pb-Free_Overlay_Medium') OR HasFootprint('Pb-Free_Overlay_Small')) vs (HasFootprint('Pb-Free_Overlay_Medium') OR HasFootprint('Pb-Free_Overlay_Small'))] p1: silktosilkclearance=0
SilkToSilkClearance [All] p2: silktosilkclearance=0.1
SilkToSolderMaskClearance SilkToComponentPadClearance [(IsPad or IsFill or IsRegion) and InAnycomponent] p1: minsilkscreentomaskgap=0.127 clearancetoexposedcopper=TRUE
SilkToSolderMaskClearance "Silk to Solder Mask Opening" [All] p2: minsilkscreentomaskgap=0.1 clearancetoexposedcopper=FALSE
SolderMaskExpansion [All] p1: expansion=0.05 istentingtop=FALSE
UnRoutedNet [All] p1: checkbadconnections=TRUE
Width MaxMinWidth_1 [All] p1: maxlimit=3 minlimit=0.2 preferedwidth=0.2 minimp=50.000000 maximp=50.000000 favimp=50.000000
14 further rules are at their usual default settings.

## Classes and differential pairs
component class U_TIDA-010957-DCAC-CAN: C6 C147 C148 C149 C150 C151 C152 C153 C154 C155 C156 C157 C158 D18 FB12 FB13 FB17 FB18 J1 J11 L3 R93 R224 R225 R226 R227 R228 U23 U24 U25
net class LN_HV: I_PCC_N+ I_PCC_N- NetF4_1 NetL12_8 PCC_N SN_LN V_PCC_N
net class L3_HV: I_PCC_L3+ I_PCC_L3- NetF3_1 NetL12_6 PCC_L3 SN_L3 V_PCC_L3
net class L2_HV: I_PCC_L2+ I_PCC_L2- NetF2_1 NetL12_4 PCC_L2 SN_L2 V_PCC_L2
net class L1_HV: I_PCC_L1+ I_PCC_L1- NetF1_1 NetL12_2 PCC_L1 SN_L1 V_PCC_L1
net class "DC PLUS": VDC+
net class "DC MINUS": VDC-_REF
net class "DC MIDDLE": Middle_Point
net class S4_SW: 5V_S4_GaN_L1 5V_S4_GaN_L2 5V_S4_GaN_L3 5V_S4_GaN_N 10V_S4_GaN_L1 10V_S4_GaN_L2 10V_S4_GaN_L3 10V_S4_GaN_N GND_S4_GaN_L1 GND_S4_GaN_L2 GND_S4_GaN_L3 GND_S4_GaN_N NetC245_L1_2 NetC245_L2_2 NetC245_L3_2 NetC245_N_2 NetC246_L1_2 NetC246_L2_2 NetC246_L3_2 NetC246_N_2 NetD16_L1_2 NetD16_L2_2 NetD16_L3_2 NetD16_N_2 NetL16_L1_1 NetL16_L2_1 NetL16_L3_1 NetL16_N_1 NetR317_L1_1 NetR317_L2_1 NetR317_L3_1 NetR317_N_1 NetR324_L1_1 NetR324_L2_1 NetR324_L3_1 NetR324_N_1 NetR327_L1_1 NetR327_L2_1 NetR327_L3_1 NetR327_N_1 VDC-_REF
net class S3_SW: 5V_S3_GaN_L1 5V_S3_GaN_L2 5V_S3_GaN_L3 5V_S3_GaN_N 10V_S3_GaN_L1 10V_S3_GaN_L2 10V_S3_GaN_L3 10V_S3_GaN_N GND_S1_GaN_L1 GND_S1_GaN_L2 GND_S1_GaN_L3 GND_S1_GaN_N GND_S3_GaN_L1 GND_S3_GaN_L2 GND_S3_GaN_L3 GND_S3_GaN_N NetC213_L1_1 NetC213_L2_1 NetC213_L3_1 NetC213_N_1 NetC226_L1_2 NetC226_L2_2 NetC226_L3_2 NetC226_N_2 NetC227_L1_2 NetC227_L2_2 NetC227_L3_2 NetC227_N_2 NetC241_L1_1 NetC241_L2_1 NetC241_L3_1 NetC241_N_1 NetC242_L1_2 NetC242_L2_2 NetC242_L3_2 NetC242_N_2 NetD12_L1_2 NetD12_L2_2 NetD12_L3_2 NetD12_N_2 NetL14_L1_1 NetL14_L2_1 NetL14_L3_1 NetL14_N_1 NetR303_L1_1 NetR303_L2_1 NetR303_L3_1 NetR303_N_1 NetR304_L1_2 NetR304_L2_2 NetR304_L3_2 NetR304_N_2 NetR307_L1_1 NetR307_L2_1 NetR307_L3_1 NetR307_N_1 NetR310_L1_1 NetR310_L2_1 NetR310_L3_1 NetR310_N_1 NetR312_L1_2 NetR312_L2_2 NetR312_L3_2 NetR312_N_2 NetR313_L1_2 NetR313_L2_2 NetR313_L3_2 NetR313_N_2
net class S2_SW: 5V_S2_GaN_L1 5V_S2_GaN_L2 5V_S2_GaN_L3 5V_S2_GaN_N 10V_S2_GaN_L1 10V_S2_GaN_L2 10V_S2_GaN_L3 10V_S2_GaN_N GND_S2_GaN_L1 GND_S2_GaN_L2 GND_S2_GaN_L3 GND_S2_GaN_N NetC202_L1_2 NetC202_L2_2 NetC202_L3_2 NetC202_N_2 NetC203_L1_2 NetC203_L2_2 NetC203_L3_2 NetC203_N_2 NetD11_L1_2 NetD11_L2_2 NetD11_L3_2 NetD11_N_2 NetL12_L1_1 NetL12_L2_1 NetL12_L3_1 NetL12_N_1 NetR292_L1_1 NetR292_L2_1 NetR292_L3_1 NetR292_N_1 NetR297_L1_1 NetR297_L2_1 NetR297_L3_1 NetR297_N_1 NetR300_L1_1 NetR300_L2_1 NetR300_L3_1 NetR300_N_1 SN_L1 SN_L2 SN_L3 SN_LN
net class S1_SW: 5V_S1_GaN_L1 5V_S1_GaN_L2 5V_S1_GaN_L3 5V_S1_GaN_N 10V_S1_GaN_L1 10V_S1_GaN_L2 10V_S1_GaN_L3 10V_S1_GaN_N GND_S1_GaN_L1 GND_S1_GaN_L2 GND_S1_GaN_L3 GND_S1_GaN_N NetC188_L1_2 NetC188_L2_2 NetC188_L3_2 NetC188_N_2 NetC189_L1_2 NetC189_L2_2 NetC189_L3_2 NetC189_N_2 NetC213_L1_2 NetC213_L2_2 NetC213_L3_2 NetC213_N_2 NetD10_L1_2 NetD10_L2_2 NetD10_L3_2 NetD10_N_2 NetL10_L1_1 NetL10_L2_1 NetL10_L3_1 NetL10_N_1 NetR279_L1_1 NetR279_L2_1 NetR279_L3_1 NetR279_N_1 NetR286_L1_1 NetR286_L2_1 NetR286_L3_1 NetR286_N_1 NetR289_L1_1 NetR289_L2_1 NetR289_L3_1 NetR289_N_1
net class "LV Nets": 3V3 12V
net class LV_NET: 1V65 3V3 5V 12V 12V_FET_DRAIN +12V_OUT AUX_IN_PWR BUFF_EN CAN_EN CAN_GND2 CAN_RX CAN_TX CAN_VDD CAN_VIO CANH CANHI CANL CANLO DC_VSEN+ DC_VSEN- DCDC_EN DCDC_FB DCDC_PG DCDC_VIN EF_dVdt EF_EN EF_ILIM EF_ITIMER EF_OVLO EF_PG EF_PGTH EN_AUX_ISO_DCAC EN_AUX_ISO_DCDC EN_BUFF_PWM_DCDC FAN_CTRL FAN_SN GND GND_HVN GND_ISO_CAN GNDP GPIO1 GPIO2 GPIO3 GPIO4 GPIOA GPIOB GPIOC GPIOD GPIOE GPIOF GPIOG GRID_RELAYS I_L1_VREF I_L2_VREF I_L3_VREF I_N_VREF I_SENSE_1 I_SENSE_2 I_SENSE_A I_SENSE_B I_SENSE_PCC_L1 I_SENSE_PCC_L2 I_SENSE_PCC_L3 I_SENSE_PCC_N I_VOUT_L1 I_VOUT_L2 I_VOUT_L3 I_VOUT_N MONITOR_GaN_ISO_L1 MONITOR_GaN_ISO_L2 MONITOR_GaN_ISO_L3 MONITOR_GaN_ISO_N MONITOR_OC_A MONITOR_OC_B MONITOR_S1_GaN_ISO_L1 MONITOR_S1_GaN_ISO_L2 MONITOR_S1_GaN_ISO_L3 MONITOR_S1_GaN_ISO_N MONITOR_S2_GaN_ISO_L1 MONITOR_S2_GaN_ISO_L2 MONITOR_S2_GaN_ISO_L3 MONITOR_S2_GaN_ISO_N MONITOR_S4_GaN_ISO_L1 MONITOR_S4_GaN_ISO_L2 MONITOR_S4_GaN_ISO_L3 MONITOR_S4_GaN_ISO_N MONITOR_TEMP_A MONITOR_TEMP_B NetC15_2 NetC28_1 NetC29_1 NetC30_1 NetC32_1 NetC32_2 NetC35_1 NetC36_1 NetC38_1 NetC38_2 NetC41_1 NetC42_1 NetC44_1 NetC44_2 NetC47_2 NetC48_1 NetC49_1 NetC51_1 NetC51_2 NetC56_2 NetC60_1 NetC63_2 NetC67_1 NetC70_2 NetC74_1 NetC77_1 NetC82_1 NetC83_2 NetC86_1 NetC86_2 NetC94_1 NetC95_2 NetC97_1 NetC97_2 NetC98_2 NetC100_1 NetC100_2 NetC101_2 NetC103_1 NetC103_2 NetC104_2 NetC106_1 NetC106_2 NetC107_1 NetC113_1 NetC114_1 NetC125_1 NetC138_1 NetC157_2 NetC196_L1_2 NetC196_L2_2 NetC196_L3_2 NetC196_N_2 NetC198_L1_1 NetC198_L2_1 NetC198_L3_1 NetC198_N_1 NetC219_L1_2 NetC219_L2_2 NetC219_L3_2 NetC219_N_2 NetC221_L1_1 NetC221_L2_1 NetC221_L3_1 NetC221_N_1 NetC236_L1_2 NetC236_L2_2 NetC236_L3_2 NetC236_N_2 NetC238_L1_1 NetC238_L2_1 NetC238_L3_1 NetC238_N_1 NetC240_L1_1 NetC240_L2_1 NetC240_L3_1 NetC240_N_1 NetC253_L1_2 NetC253_L2_2 NetC253_L3_2 NetC253_N_2 NetC255_L1_1 NetC255_L2_1 NetC255_L3_1 NetC255_N_1 NetC261_1 NetC262_1 NetD1_1 NetD1_2 NetD2_1 NetD2_2 NetD4_1 NetD6_1 NetD18_1 NetJ4_3 NetJ6_3 NetJ12_1 NetJ12_2 NetJ12_3 NetJ12_4 NetJ12_5 NetJ12_6 NetJ12_8 NetJ12_9 NetJ12_11 NetJ12_12 NetJ12_13 NetJ12_14 NetJ12_15 NetJ12_17 NetJ12_18 NetJ12_20 NetJ12_21 NetJ12_23 NetJ12_24 NetJ12_25 NetJ12_26 NetJ12_27 NetJ12_28 NetJ12_30 NetJ12_31 NetJ12_32 NetJ12_33 NetJ12_34 NetJ12_36 NetJ12_37 NetJ12_39 NetJ12_40 NetJ12_41 NetJ12_42 NetJ12_43 NetJ12_44 NetJ12_45 NetJ12_49 NetJ12_50 NetJ12_51 NetJ12_52 NetJ12_53 NetJ12_54 NetJ12_55 NetJ12_56 NetJ12_57 NetJ12_58 NetJ12_59 NetJ12_60 NetJ12_61 NetJ12_62 NetJ12_63 NetJ12_64 NetJ12_66 NetJ12_67 NetJ12_69 NetJ12_70 NetJ12_71 NetJ12_72 NetJ12_73 NetJ12_74 NetJ12_75 NetJ12_76 NetJ12_77 NetJ12_78 NetJ12_79 NetJ12_80 NetJ12_81 NetJ12_82 NetJ12_85 NetJ12_87 NetJ12_89 NetJ12_91 NetJ12_93 NetJ12_95 NetJ12_99 NetJ12_101 NetJ12_103 NetJ12_105 NetJ12_108 NetJ12_110 NetJ12_113 NetJ12_114 NetJ12_115 NetJ12_116 NetJ12_117 NetJ12_118 NetJ12_119 NetJ12_120 NetJ21_3 NetR19_2 NetR130_1 NetR132_1 NetR134_1 NetR136_2 NetR143_2 NetR165_1 NetR166_1 NetR167_1 NetR168_1 NetR176_1 NetR177_1 NetR178_1 NetR179_1 NetR180_1 NetR181_1 NetR182_1 NetR183_1 NetR195_1 NetR196_1 NetR197_1 NetR198_1 NetR278_L1_2 NetR278_L2_2 NetR278_L3_2 NetR278_N_2 NetR291_L1_2 NetR291_L2_2 NetR291_L3_2 NetR291_N_2 NetR293_L1_2 NetR293_L2_2 NetR293_L3_2 NetR293_N_2 NetR302_L1_2 NetR302_L2_2 NetR302_L3_2 NetR302_N_2 NetR316_L1_2 NetR316_L2_2 NetR316_L3_2 NetR316_N_2 NetR332_2 NetU1_2 NetU2_8 NetU2_10 NetU4_8 NetU4_10 NetU5_8 NetU5_10 NetU6_8 NetU6_10 NetU11_7 NetU11_8 NetU11_12 NetU11_13 NetU11_15 NetU20_9 NetU21_2 OC_A OC_B OC_L1 OC_L2 OC_L3 OC_N PWM_S1_GaN_A PWM_S1_GaN_B PWM_S1_GaN_BUF_L1 PWM_S1_GaN_BUF_L2 PWM_S1_GaN_BUF_L3 PWM_S1_GaN_BUF_N PWM_S1_GaN_L1 PWM_S1_GaN_L2 PWM_S1_GaN_L3 PWM_S1_GaN_N PWM_S2_GaN_A PWM_S2_GaN_B PWM_S2_GaN_BUF_L1 PWM_S2_GaN_BUF_L2 PWM_S2_GaN_BUF_L3 PWM_S2_GaN_BUF_N PWM_S2_GaN_L1 PWM_S2_GaN_L2 PWM_S2_GaN_L3 PWM_S2_GaN_N PWM_S3_GaN_A PWM_S3_GaN_B PWM_S3_GaN_BUF_L1 PWM_S3_GaN_BUF_L2 PWM_S3_GaN_BUF_L3 PWM_S3_GaN_BUF_N PWM_S3_GaN_L1 PWM_S3_GaN_L2 PWM_S3_GaN_L3 PWM_S3_GaN_N PWM_S4_GaN_A PWM_S4_GaN_B PWM_S4_GaN_BUF_L1 PWM_S4_GaN_BUF_L2 PWM_S4_GaN_BUF_L3 PWM_S4_GaN_BUF_N PWM_S4_GaN_L1 PWM_S4_GaN_L2 PWM_S4_GaN_L3 PWM_S4_GaN_N SN_Relays T_HEATSINK_DCAC T_HEATSINK_DCDC TEMP_S3_GaN_ISO_L1 TEMP_S3_GaN_ISO_L2 TEMP_S3_GaN_ISO_L3 TEMP_S3_GaN_ISO_N V_FC_L1 V_FC_L2 V_FC_L3 V_FC_N V_FC_NEG_L1 V_FC_NEG_L2 V_FC_NEG_L3 V_FC_NEG_N V_FC_POS_L1 V_FC_POS_L2 V_FC_POS_L3 V_FC_POS_N V_SENSE_1 V_SENSE_2 V_SENSE_3 V_SENSE_DC V_SENSE_PCC_L1 V_SENSE_PCC_L2 V_SENSE_PCC_L3 VIN_PWR VIN_PWR_CAN VINP_DC-_HAVOK VISOOUT VP_CAN VP_CAN_SUBD
net class HV_NET: 5V_S1_GaN_L1 5V_S1_GaN_L2 5V_S1_GaN_L3 5V_S1_GaN_N 5V_S2_GaN_L1 5V_S2_GaN_L2 5V_S2_GaN_L3 5V_S2_GaN_N 5V_S3_GaN_L1 5V_S3_GaN_L2 5V_S3_GaN_L3 5V_S3_GaN_N 5V_S4_GaN_L1 5V_S4_GaN_L2 5V_S4_GaN_L3 5V_S4_GaN_N 10V_S1_GaN_L1 10V_S1_GaN_L2 10V_S1_GaN_L3 10V_S1_GaN_N 10V_S2_GaN_L1 10V_S2_GaN_L2 10V_S2_GaN_L3 10V_S2_GaN_N 10V_S3_GaN_L1 10V_S3_GaN_L2 10V_S3_GaN_L3 10V_S3_GaN_N 10V_S4_GaN_L1 10V_S4_GaN_L2 10V_S4_GaN_L3 10V_S4_GaN_N GND_S1_GaN_L1 GND_S1_GaN_L2 GND_S1_GaN_L3 GND_S1_GaN_N GND_S2_GaN_L1 GND_S2_GaN_L2 GND_S2_GaN_L3 GND_S2_GaN_N GND_S3_GaN_L1 GND_S3_GaN_L2 GND_S3_GaN_L3 GND_S3_GaN_N GND_S4_GaN_L1 GND_S4_GaN_L2 GND_S4_GaN_L3 GND_S4_GaN_N GRID_GND GRID_GND_1 I_PCC_L1+ I_PCC_L1- I_PCC_L2+ I_PCC_L2- I_PCC_L3+ I_PCC_L3- I_PCC_N+ I_PCC_N- Middle_Point NetC188_L1_2 NetC188_L2_2 NetC188_L3_2 NetC188_N_2 NetC189_L1_2 NetC189_L2_2 NetC189_L3_2 NetC189_N_2 NetC202_L1_2 NetC202_L2_2 NetC202_L3_2 NetC202_N_2 NetC203_L1_2 NetC203_L2_2 NetC203_L3_2 NetC203_N_2 NetC213_L1_1 NetC213_L1_2 NetC213_L2_1 NetC213_L2_2 NetC213_L3_1 NetC213_L3_2 NetC213_N_1 NetC213_N_2 NetC226_L1_2 NetC226_L2_2 NetC226_L3_2 NetC226_N_2 NetC227_L1_2 NetC227_L2_2 NetC227_L3_2 NetC227_N_2 NetC241_L1_1 NetC241_L2_1 NetC241_L3_1 NetC241_N_1 NetC242_L1_2 NetC242_L2_2 NetC242_L3_2 NetC242_N_2 NetC245_L1_2 NetC245_L2_2 NetC245_L3_2 NetC245_N_2 NetC246_L1_2 NetC246_L2_2 NetC246_L3_2 NetC246_N_2 NetD7_L1_2 NetD7_L2_2 NetD7_L3_2 NetD7_N_2 NetD8_L1_1 NetD8_L1_2 NetD8_L2_1 NetD8_L2_2 NetD8_L3_1 NetD8_L3_2 NetD8_N_1 NetD8_N_2 NetD10_L1_2 NetD10_L2_2 NetD10_L3_2 NetD10_N_2 NetD11_L1_2 NetD11_L2_2 NetD11_L3_2 NetD11_N_2 NetD12_L1_2 NetD12_L2_2 NetD12_L3_2 NetD12_N_2 NetD13_L1_1 NetD13_L1_2 NetD13_L2_1 NetD13_L2_2 NetD13_L3_1 NetD13_L3_2 NetD13_N_1 NetD13_N_2 NetD14_L1_1 NetD14_L2_1 NetD14_L3_1 NetD14_N_1 NetD16_L1_2 NetD16_L2_2 NetD16_L3_2 NetD16_N_2 NetF1_1 NetF2_1 NetF3_1 NetF4_1 NetL10_L1_1 NetL10_L2_1 NetL10_L3_1 NetL10_N_1 NetL12_2 NetL12_4 NetL12_6 NetL12_8 NetL12_L1_1 NetL12_L2_1 NetL12_L3_1 NetL12_N_1 NetL14_L1_1 NetL14_L2_1 NetL14_L3_1 NetL14_N_1 NetL16_L1_1 NetL16_L2_1 NetL16_L3_1 NetL16_N_1 NetR1_1 NetR4_1 NetR10_1 NetR13_1 NetR279_L1_1 NetR279_L2_1 NetR279_L3_1 NetR279_N_1 NetR286_L1_1 NetR286_L2_1 NetR286_L3_1 NetR286_N_1 NetR289_L1_1 NetR289_L2_1 NetR289_L3_1 NetR289_N_1 NetR292_L1_1 NetR292_L2_1 NetR292_L3_1 NetR292_N_1 NetR297_L1_1 NetR297_L2_1 NetR297_L3_1 NetR297_N_1 NetR300_L1_1 NetR300_L2_1 NetR300_L3_1 NetR300_N_1 NetR303_L1_1 NetR303_L2_1 NetR303_L3_1 NetR303_N_1 NetR304_L1_2 NetR304_L2_2 NetR304_L3_2 NetR304_N_2 NetR307_L1_1 NetR307_L2_1 NetR307_L3_1 NetR307_N_1 NetR310_L1_1 NetR310_L2_1 NetR310_L3_1 NetR310_N_1 NetR312_L1_2 NetR312_L2_2 NetR312_L3_2 NetR312_N_2 NetR313_L1_2 NetR313_L2_2 NetR313_L3_2 NetR313_N_2 NetR317_L1_1 NetR317_L2_1 NetR317_L3_1 NetR317_N_1 NetR324_L1_1 NetR324_L2_1 NetR324_L3_1 NetR324_N_1 NetR327_L1_1 NetR327_L2_1 NetR327_L3_1 NetR327_N_1 PCC_L1 PCC_L2 PCC_L3 PCC_N SN_L1 SN_L2 SN_L3 SN_LN V_PCC_L1 V_PCC_L2 V_PCC_L3 V_PCC_N VDC+ VDC-_REF
channel class TIDA-010957-DCAC-Switching-Stage-GaN-TOLT: L1 L2 L3 N
component class L3: C186_L3 C187_L3 C188_L3 C189_L3 C190_L3 C191_L3 C192_L3 C193_L3 C194_L3 C195_L3 C196_L3 C197_L3 C198_L3 C199_L3 C200_L3 C201_L3 C202_L3 C203_L3 C204_L3 C205_L3 C206_L3 C207_L3 C208_L3 C209_L3 C210_L3 C211_L3 C212_L3 C213_L3 C215_L3 C216_L3 C217_L3 C219_L3 C220_L3 C221_L3 C222_L3 C223_L3 C224_L3 C225_L3 C226_L3 C227_L3 C228_L3 C229_L3 C230_L3 C231_L3 C232_L3 C233_L3 C234_L3 C235_L3 C236_L3 C237_L3 C238_L3 C239_L3 C240_L3 C241_L3 C242_L3 C243_L3 C244_L3 C245_L3 C246_L3 C247_L3 C248_L3 C249_L3 C250_L3 C251_L3 C252_L3 C253_L3 C254_L3 C255_L3 C256_L3 D7_L3 D8_L3 D9_L3 D10_L3 D11_L3 D12_L3 D13_L3 D14_L3 D15_L3 D16_L3 FB14_L3 FB15_L3 L10_L3 L11_L3 L12_L3 L13_L3 L14_L3 L15_L3 L16_L3 L17_L3 R278_L3 R279_L3 R281_L3 R282_L3 R283_L3 R284_L3 R285_L3 R286_L3 R287_L3 R288_L3 R289_L3 R290_L3 R291_L3 R292_L3 R293_L3 R294_L3 R295_L3 R296_L3 R297_L3 R298_L3 R299_L3 R300_L3 R301_L3 R302_L3 R303_L3 R304_L3 R305_L3 R306_L3 R307_L3 R308_L3 R309_L3 R310_L3 R311_L3 R312_L3 R313_L3 R314_L3 R315_L3 R316_L3 R317_L3 R319_L3 R320_L3 R321_L3 R322_L3 R323_L3 R324_L3 R325_L3 R326_L3 R327_L3 R328_L3 U27_L3 U28_L3 U29_L3 U30_L3 U31_L3 U32_L3 U33_L3 U34_L3 U35_L3 U36_L3 U37_L3 U38_L3 U39_L3 U40_L3 U41_L3 U42_L3 U43_L3 U44_L3 U45_L3
component class L2: C186_L2 C187_L2 C188_L2 C189_L2 C190_L2 C191_L2 C192_L2 C193_L2 C194_L2 C195_L2 C196_L2 C197_L2 C198_L2 C199_L2 C200_L2 C201_L2 C202_L2 C203_L2 C204_L2 C205_L2 C206_L2 C207_L2 C208_L2 C209_L2 C210_L2 C211_L2 C212_L2 C213_L2 C215_L2 C216_L2 C217_L2 C219_L2 C220_L2 C221_L2 C222_L2 C223_L2 C224_L2 C225_L2 C226_L2 C227_L2 C228_L2 C229_L2 C230_L2 C231_L2 C232_L2 C233_L2 C234_L2 C235_L2 C236_L2 C237_L2 C238_L2 C239_L2 C240_L2 C241_L2 C242_L2 C243_L2 C244_L2 C245_L2 C246_L2 C247_L2 C248_L2 C249_L2 C250_L2 C251_L2 C252_L2 C253_L2 C254_L2 C255_L2 C256_L2 D7_L2 D8_L2 D9_L2 D10_L2 D11_L2 D12_L2 D13_L2 D14_L2 D15_L2 D16_L2 FB14_L2 FB15_L2 L10_L2 L11_L2 L12_L2 L13_L2 L14_L2 L15_L2 L16_L2 L17_L2 R278_L2 R279_L2 R281_L2 R282_L2 R283_L2 R284_L2 R285_L2 R286_L2 R287_L2 R288_L2 R289_L2 R290_L2 R291_L2 R292_L2 R293_L2 R294_L2 R295_L2 R296_L2 R297_L2 R298_L2 R299_L2 R300_L2 R301_L2 R302_L2 R303_L2 R304_L2 R305_L2 R306_L2 R307_L2 R308_L2 R309_L2 R310_L2 R311_L2 R312_L2 R313_L2 R314_L2 R315_L2 R316_L2 R317_L2 R319_L2 R320_L2 R321_L2 R322_L2 R323_L2 R324_L2 R325_L2 R326_L2 R327_L2 R328_L2 U27_L2 U28_L2 U29_L2 U30_L2 U31_L2 U32_L2 U33_L2 U34_L2 U35_L2 U36_L2 U37_L2 U38_L2 U39_L2 U40_L2 U41_L2 U42_L2 U43_L2 U44_L2 U45_L2
component class L1: C186_L1 C187_L1 C188_L1 C189_L1 C190_L1 C191_L1 C192_L1 C193_L1 C194_L1 C195_L1 C196_L1 C197_L1 C198_L1 C199_L1 C200_L1 C201_L1 C202_L1 C203_L1 C204_L1 C205_L1 C206_L1 C207_L1 C208_L1 C209_L1 C210_L1 C211_L1 C212_L1 C213_L1 C215_L1 C216_L1 C217_L1 C219_L1 C220_L1 C221_L1 C222_L1 C223_L1 C224_L1 C225_L1 C226_L1 C227_L1 C228_L1 C229_L1 C230_L1 C231_L1 C232_L1 C233_L1 C234_L1 C235_L1 C236_L1 C237_L1 C238_L1 C239_L1 C240_L1 C241_L1 C242_L1 C243_L1 C244_L1 C245_L1 C246_L1 C247_L1 C248_L1 C249_L1 C250_L1 C251_L1 C252_L1 C253_L1 C254_L1 C255_L1 C256_L1 D7_L1 D8_L1 D9_L1 D10_L1 D11_L1 D12_L1 D13_L1 D14_L1 D15_L1 D16_L1 FB14_L1 FB15_L1 L10_L1 L11_L1 L12_L1 L13_L1 L14_L1 L15_L1 L16_L1 L17_L1 R278_L1 R279_L1 R281_L1 R282_L1 R283_L1 R284_L1 R285_L1 R286_L1 R287_L1 R288_L1 R289_L1 R290_L1 R291_L1 R292_L1 R293_L1 R294_L1 R295_L1 R296_L1 R297_L1 R298_L1 R299_L1 R300_L1 R301_L1 R302_L1 R303_L1 R304_L1 R305_L1 R306_L1 R307_L1 R308_L1 R309_L1 R310_L1 R311_L1 R312_L1 R313_L1 R314_L1 R315_L1 R316_L1 R317_L1 R319_L1 R320_L1 R321_L1 R322_L1 R323_L1 R324_L1 R325_L1 R326_L1 R327_L1 R328_L1 U27_L1 U28_L1 U29_L1 U30_L1 U31_L1 U32_L1 U33_L1 U34_L1 U35_L1 U36_L1 U37_L1 U38_L1 U39_L1 U40_L1 U41_L1 U42_L1 U43_L1 U44_L1 U45_L1
component class U_TIDA-010957-Mechanics: !PCB1 C4 C13 C14 C259 C260 C261 D17 FID1 FID2 FID3 J4 J6 J21 LBL1 Logo1 Logo2 Logo3 Logo4 MP1 MP2 MP3 MP4 MP5 MP6 MP7 MP8 MP9 MP10 MP11 MP12 MP13 MP14 MP15 Q3 R19 R329 R330 U1 ZZ1 ZZ2 ZZ3 ZZ4
component class Logo: Logo2
component class Label: LBL1
component class FiducialMark: FID1 FID2 FID3
component class AssemblyNote: ZZ1 ZZ2 ZZ3 ZZ4
component class N: C186_N C187_N C188_N C189_N C190_N C191_N C192_N C193_N C194_N C195_N C196_N C197_N C198_N C199_N C200_N C201_N C202_N C203_N C204_N C205_N C206_N C207_N C208_N C209_N C210_N C211_N C212_N C213_N C215_N C216_N C217_N C219_N C220_N C221_N C222_N C223_N C224_N C225_N C226_N C227_N C228_N C229_N C230_N C231_N C232_N C233_N C234_N C235_N C236_N C237_N C238_N C239_N C240_N C241_N C242_N C243_N C244_N C245_N C246_N C247_N C248_N C249_N C250_N C251_N C252_N C253_N C254_N C255_N C256_N D7_N D8_N D9_N D10_N D11_N D12_N D13_N D14_N D15_N D16_N FB14_N FB15_N L10_N L11_N L12_N L13_N L14_N L15_N L16_N L17_N R278_N R279_N R281_N R282_N R283_N R284_N R285_N R286_N R287_N R288_N R289_N R290_N R291_N R292_N R293_N R294_N R295_N R296_N R297_N R298_N R299_N R300_N R301_N R302_N R303_N R304_N R305_N R306_N R307_N R308_N R309_N R310_N R311_N R312_N R313_N R314_N R315_N R316_N R317_N R319_N R320_N R321_N R322_N R323_N R324_N R325_N R326_N R327_N R328_N U27_N U28_N U29_N U30_N U31_N U32_N U33_N U34_N U35_N U36_N U37_N U38_N U39_N U40_N U41_N U42_N U43_N U44_N U45_N
component class U_TIDA-010957-DCAC-PWM-BUFFER: C107 C108 C109 C110 C111 C112 C113 C114 C115 C116 C117 C118 C119 C120 C121 C122 C123 C124 C125 C126 C127 C128 C129 C130 R164 R165 R166 R167 R168 R169 R170 R171 R172 R173 R174 R175 R176 R177 R178 R179 R180 R181 R182 R183 R184 R185 R186 R187 R188 R189 R190 R191 R192 R193 R194 R195 R196 R197 R198 R199 R200 R201 R202 R203 U15 U16 U17 U18
component class U_TIDA-010957-DCAC-Power-Tree: C131 C132 C133 C134 C135 C136 C137 C138 C139 C140 C141 C142 C143 C144 C145 C146 D4 D5 D6 J14 J15 J16 J17 J18 Q2 R204 R205 R206 R207 R208 R209 R210 R211 R212 R213 R214 R215 R216 R217 R218 R219 TP5 TP6 U19 U20 U21 U22
component class U_TIDA-010957-DCAC-EMI-Filter: C17 C18 C19 C20 C21 C22 C23 C24 C25 C26 C27 C28 C257 C258 D3 F1 F2 F3 F4 L1 L2 L5 L6 L12 L19 N Q1 R83 R85 R87 R89 R90 R91 R92 R94 R96 R97 R220 R221 R222 R223 TP2 TP3 TP4 TP7
component class U_TIDA-010957-CONTROLLER: C5 C15 C16 C159 C160 C161 C162 D1 D2 FB1 J12 J13 R20 R21 R22 R23 R24 R25 R26 R27 R28 R29 R30 R31 R32 R33 R34 R35 R36 R37 R38 R39 R40 R41 R42 R43 R44 R45 R46 R47 R48 R49 R50 R51 R52 R53 R54 R55 R56 R57 R58 R59 R60 R61 R62 R63 R64 R65 R66 R67 R68 R69 R70 R71 R72 R73 R74 R75 R76 R77 R78 R79 R80 R81 R82 R84 R86 R88 R334 TP1 TP11 TP12 TP13
component class TIDA-010957-DCAC-Overview: C1 C2 C3 C7 C8 C9 C10 C11 C12 J2 J3 J5 J7 J8 J9 J10 R1 R2 R3 R4 R5 R6 R7 R8 R9 R10 R11 R12 R13 R14 R15 R16 R17 R18 TP8 TP9 TP10
component class TIDA-010957-DCAC-Measurements-Voltages-AC: C54 C55 C56 C57 C58 C59 C60 C61 C62 C63 C64 C65 C66 C67 C68 C69 C70 C71 C72 C73 C74 C75 C76 C77 C78 C79 FB7 FB8 FB9 FB10 L7 R130 R131 R132 R133 R134 R135 R136 RN1 RN2 RN3 U7 U8 U9 U10
component class TIDA-010957-DCAC-FC-OP-AMP: C94 C95 C96 C97 C98 C99 C100 C101 C102 C103 C104 C105 C106 FB11 R144 R145 R146 R147 R148 R149 R150 R151 R152 R153 R154 R155 R156 R157 R158 R159 R160 R161 R162 R163 U14
component class TIDA-010957-DCAC-Current-Sensing: C29 C30 C31 C32 C33 C34 C35 C36 C37 C38 C39 C40 C41 C42 C43 C44 C45 C46 C47 C48 C49 C50 C51 C52 C53 FB2 FB3 FB4 FB5 FB6 R98 R99 R100 R101 R102 R103 R104 R105 R106 R107 R108 R109 R110 R111 R112 R113 R114 R115 R116 R117 R118 R119 R120 R121 R122 R123 R124 R125 R126 R127 R128 R129 U2 U3 U4 U5 U6
component class TIDA-010957-DC-Voltage-Measurements: C80 C81 C82 C83 C84 C85 C86 C87 C88 C89 C90 C91 C92 C93 C262 C263 FB16 L8 L9 R137 R138 R139 R140 R141 R142 R143 R331 R332 R333 U11 U12 U13
component class Header: J11 J13 J14 J15 J17 J18

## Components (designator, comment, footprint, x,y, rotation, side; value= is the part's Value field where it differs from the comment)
C1 "ALA7DA301CF550" FP-ALA7DA301CF550_RADIAL-MFG 47.834,85 r0 top value=300µF
C2 "ALA7DA301CF550" FP-ALA7DA301CF550_RADIAL-MFG 16,220 r0 top locked value=300µF
C3 "ALA7DA301CF550" FP-ALA7DA301CF550_RADIAL-MFG 16,188 r0 top locked value=300µF
C4 "EEU-FM1E101" FM_630x1120 149.623,3.586 r0 top value=100uF
C5 "CGA3E2C0G1H331J080AA" FP-CGA3E2C0G1H331J080AA_0603-MFG 279.6,42.5 r0 top value=330pF
C6 "CL31B106KBHNNNE" 1206_180L 286.7,38 r180 top value=10uF
C7 "ALA7DA301CF550" FP-ALA7DA301CF550_RADIAL-MFG 15.846,85 r0 top value=300µF
C8 "ALA7DA301CF550" FP-ALA7DA301CF550_RADIAL-MFG 16,156 r180 top locked value=300µF
C9 "ALA7DA301CF550" FP-ALA7DA301CF550_RADIAL-MFG 16,121.936 r180 top locked value=300µF
C10 "B32774X1305K000" FP-B32774X1305K000_RADIAL-MFG 80.529,79.135 r180 top value=3µF
C11 "B32774X1305K000" FP-B32774X1305K000_RADIAL-MFG 108,165.8 r90 top value=3µF
C12 "B32774X1305K000" FP-B32774X1305K000_RADIAL-MFG 192,155.75 r90 top value=3µF
C13 "06033C104JAT2A" 0603 190.3,80.5 r0 top value=0.1uF
C14 "CGA3E2C0G1H331J080AA" FP-CGA3E2C0G1H331J080AA_0603-MFG 232.1,34.3 r270 top value=330pF
C15 "TMK107BJ105KA-T" 0603 198.3,37.9 r0 top value=1uF
C16 "06033C104JAT2A" 0603 198.4,36 r180 top value=0.1uF
C17 "R523R447050P1M" FP-R523R447050P1M_RADIAL-MFG 16.25,260 r0 top value=4.7µF
C18 "R523R447050P1M" FP-R523R447050P1M_RADIAL-MFG 16.25,276 r0 top value=4.7µF
C19 "R523R447050P1M" FP-R523R447050P1M_RADIAL-MFG 16.25,244 r0 top value=4.7µF
C20 "R523R447050P1M" FP-R523R447050P1M_RADIAL-MFG 132,283.25 r90 top value=4.7µF
C21 "R523R447050P1M" FP-R523R447050P1M_RADIAL-MFG 116,283.25 r90 top value=4.7µF
C22 "R523R447050P1M" FP-R523R447050P1M_RADIAL-MFG 100,283.25 r90 top value=4.7µF
C23 "B58043E5254M052" FP-B58043E5254M052_2220-MFG 8.75,242.771 r0 bottom value=250nF
C24 "R413F147050T1K" FP-R413F147050T1K_RADIAL-MFG 32,293 r270 top value=4.7nF
C25 "R413F147050T1K" FP-R413F147050T1K_RADIAL-MFG 85.5,297 r0 top value=4.7nF
C26 "EEU-FM1E101" FM_630x1120 293.75,212.6 r0 top value=100uF
C27 "06033C104JAT2A" 0603 291.8,206.9 r270 top value=0.1uF
C28 "06033C104JAT2A" 0603 289,204 r0 top value=0.1uF
C29 "CGA3E2C0G1H331J080AA" FP-CGA3E2C0G1H331J080AA_0603-MFG 271.549,43.726 r180 top value=330pF
C30 "06033C104JAT2A" 0603 98,238 r0 top value=0.1uF
C31 "CGA3E2C0G1H331J080AA" FP-CGA3E2C0G1H331J080AA_0603-MFG 246,54.4 r270 top value=330pF
C32 "CGA3E2C0G1H331J080AA" FP-CGA3E2C0G1H331J080AA_0603-MFG 269.116,43.791 r180 top value=330pF
C33 "CGA3E2C0G1H331J080AA" FP-CGA3E2C0G1H331J080AA_0603-MFG 217.2,55 r180 top value=330pF
C34 "06033C104JAT2A" 0603 98,243.3 r180 top value=0.1uF
C35 "CGA3E2C0G1H331J080AA" FP-CGA3E2C0G1H331J080AA_0603-MFG 277.617,44.482 r270 top value=330pF
C36 "06033C104JAT2A" 0603 112.2,228.1 r0 top value=0.1uF
C37 "CGA3E2C0G1H331J080AA" FP-CGA3E2C0G1H331J080AA_0603-MFG 240.9,32.6 r90 top value=330pF
C38 "CGA3E2C0G1H331J080AA" FP-CGA3E2C0G1H331J080AA_0603-MFG 274.389,43.409 r180 top value=330pF
C39 "CGA3E2C0G1H331J080AA" FP-CGA3E2C0G1H331J080AA_0603-MFG 215.4,53.3 r180 top value=330pF
C40 "06033C104JAT2A" 0603 105.4,230.5 r180 top value=0.1uF
C41 "CGA3E2C0G1H331J080AA" FP-CGA3E2C0G1H331J080AA_0603-MFG 278.8,47.719 r0 top value=330pF
C42 "06033C104JAT2A" 0603 197.1,205.2 r90 top value=0.1uF
C43 "CGA3E2C0G1H331J080AA" FP-CGA3E2C0G1H331J080AA_0603-MFG 247.8,54.4 r270 top value=330pF
C44 "CGA3E2C0G1H331J080AA" FP-CGA3E2C0G1H331J080AA_0603-MFG 277.537,49.85 r270 top value=330pF
C45 "CGA3E2C0G1H331J080AA" FP-CGA3E2C0G1H331J080AA_0603-MFG 211.4,55.7 r90 top value=330pF
C46 "06033C104JAT2A" 0603 191.8,205.6 r90 top value=0.1uF
C47 "06033C104JAT2A" 0603 267.4,46 r90 top value=0.1uF
C48 "CGA3E2C0G1H331J080AA" FP-CGA3E2C0G1H331J080AA_0603-MFG 267.25,49.4 r180 top value=330pF
C49 "06033C104JAT2A" 0603 46.4,104.5 r0 top value=0.1uF
C50 "CGA3E2C0G1H331J080AA" FP-CGA3E2C0G1H331J080AA_0603-MFG 242.1,57.3 r270 top value=330pF
C51 "CGA3E2C0G1H331J080AA" FP-CGA3E2C0G1H331J080AA_0603-MFG 270.25,51.346 r0 top value=330pF
C52 "CGA3E2C0G1H331J080AA" FP-CGA3E2C0G1H331J080AA_0603-MFG 187.3,51.1 r0 top value=330pF
C53 "06033C104JAT2A" 0603 40.425,110.9 r0 top value=0.1uF
C54 "EMK107BB7225KA-T" 0603 125.4,260.9 r270 top value=2.2uF
C55 "06033C104JAT2A" 0603 123.65,260.9 r90 top value=0.1uF
C56 "06033C104JAT2A" 0603 135.394,247.079 r90 top value=0.1uF
C57 "EMK107BB7225KA-T" 0603 137.3,247.1 r270 top value=2.2uF
C58 "CGA2B2C0G1H102J050BA" 0402L 133.12,262.85 r180 top value=1000pF
C59 "CGA3E2C0G1H331J080AA" FP-CGA3E2C0G1H331J080AA_0603-MFG 243.5,32.6 r90 top value=330pF
C60 "06033C104JAT2A" 0603 130.9,247.6 r180 top value=0.1uF
C61 "EMK107BB7225KA-T" 0603 113.7,261 r270 top value=2.2uF
C62 "06033C104JAT2A" 0603 111.95,261 r90 top value=0.1uF
C63 "06033C104JAT2A" 0603 121.221,246.802 r90 top value=0.1uF
C64 "EMK107BB7225KA-T" 0603 123.02,246.802 r270 top value=2.2uF
C65 "CGA2B2C0G1H102J050BA" 0402L 119.07,262.699 r180 top value=1000pF
C66 "CGA3E2C0G1H331J080AA" FP-CGA3E2C0G1H331J080AA_0603-MFG 238.2,57.3 r270 top value=330pF
C67 "06033C104JAT2A" 0603 116.9,247.5 r180 top value=0.1uF
C68 "EMK107BB7225KA-T" 0603 139.089,261.03 r270 top value=2.2uF
C69 "06033C104JAT2A" 0603 137.339,261.03 r90 top value=0.1uF
C70 "06033C104JAT2A" 0603 110.2,247 r90 top value=0.1uF
C71 "EMK107BB7225KA-T" 0603 112.1,247 r270 top value=2.2uF
C72 "CGA2B2C0G1H102J050BA" 0402L 107.77,262.799 r180 top value=1000pF
C73 "CGA3E2C0G1H331J080AA" FP-CGA3E2C0G1H331J080AA_0603-MFG 239.2,32.6 r90 top value=330pF
C74 "06033C104JAT2A" 0603 105.7,247.6 r180 top value=0.1uF
C75 "GRM21BZ71A226ME15L" 0805_HV 99,262.5 r180 bottom value=22uF
C76 "06033C104JAT2A" 0603 99.058,262.896 r180 top value=0.1uF
C77 "06033C104JAT2A" 0603 98.7,248.7 r0 top value=0.1uF
C78 "GRM21BZ71A226ME15L" 0805_HV 98.4,246.8 r0 top value=22uF
C79 "GRM21BZ71A226ME15L" 0805_HV 101,244.1 r270 top value=22uF
C80 "EMK107BB7225KA-T" 0603 78.375,106.45 r270 top value=2.2uF
C81 "06033C104JAT2A" 0603 80.275,106.45 r90 top value=0.1uF
C82 "06033C104JAT2A" 0603 262.5,62.6 r180 top value=0.1uF
C83 "CGA2B2C0G1H102J050BA" 0402L 255.4,57.5 r90 top value=1000pF
C84 "CGA3E2C0G1H331J080AA" FP-CGA3E2C0G1H331J080AA_0603-MFG 237.5,32.6 r270 top value=330pF
C85 "GRM155R71H102KA01D" 0402L 89.129,90.768 r180 bottom value=1000pF
C86 "CGA2B2C0G1H102J050BA" 0402L 255.205,60.013 r90 top value=1000pF
C87 "EMK107BB7225KA-T" 0603 87.929,88.798 r0 bottom value=2.2uF
C88 "06033C104JAT2A" 0603 87.929,90.418 r180 top value=0.1uF
C89 "GRM21BZ71A226ME15L" 0805_HV 95.1,89.1 r0 bottom value=22uF
C90 "06033C104JAT2A" 0603 95.113,91.033 r0 top value=0.1uF
C91 "06033C104JAT2A" 0603 95.7,105.1 r180 top value=0.1uF
C92 "GRM21BZ71A226ME15L" 0805_HV 95.913,106.956 r180 top value=22uF
C93 "GRM21BZ71A226ME15L" 0805_HV 93,106.2 r270 top value=22uF
C94 "06033C104JAT2A" 0603 176.351,74.304 r90 top value=0.1uF
C95 "CGA3E2C0G1H331J080AA" FP-CGA3E2C0G1H331J080AA_0603-MFG 180.2,75.1 r270 top value=330pF
C96 "CGA3E2C0G1H331J080AA" FP-CGA3E2C0G1H331J080AA_0603-MFG 239.9,57.3 r90 top value=330pF
C97 "CGA3E2C0G1H331J080AA" FP-CGA3E2C0G1H331J080AA_0603-MFG 182.519,72.084 r270 top value=330pF
C98 "CGA3E2C0G1H331J080AA" FP-CGA3E2C0G1H331J080AA_0603-MFG 175.532,76.829 r180 top value=330pF
C99 "CGA3E2C0G1H331J080AA" FP-CGA3E2C0G1H331J080AA_0603-MFG 248.4,32.6 r270 top value=330pF
C100 "CGA3E2C0G1H331J080AA" FP-CGA3E2C0G1H331J080AA_0603-MFG 173.515,73.401 r180 top value=330pF
C101 "CGA3E2C0G1H331J080AA" FP-CGA3E2C0G1H331J080AA_0603-MFG 175.876,63.625 r180 top value=330pF
C102 "CGA3E2C0G1H331J080AA" FP-CGA3E2C0G1H331J080AA_0603-MFG 245.1,32.6 r270 top value=330pF
C103 "CGA3E2C0G1H331J080AA" FP-CGA3E2C0G1H331J080AA_0603-MFG 173.22,63.583 r180 top value=330pF
C104 "CGA3E2C0G1H331J080AA" FP-CGA3E2C0G1H331J080AA_0603-MFG 178.457,63.625 r0 top value=330pF
C105 "CGA3E2C0G1H331J080AA" FP-CGA3E2C0G1H331J080AA_0603-MFG 246.7,32.6 r270 top value=330pF
C106 "CGA3E2C0G1H331J080AA" FP-CGA3E2C0G1H331J080AA_0603-MFG 180.961,63.583 r0 top value=330pF
C107 "06033C104JAT2A" 0603 231.4,64.6 r180 top value=0.1uF
C108 "GRM1555C1H101JA01D" 0402L 226.7,64.7 r90 top value=100pF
